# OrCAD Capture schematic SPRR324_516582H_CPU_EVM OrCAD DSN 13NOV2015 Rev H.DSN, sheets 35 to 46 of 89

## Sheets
35 SH42 - VAYU IO POWER: size B; rev: F
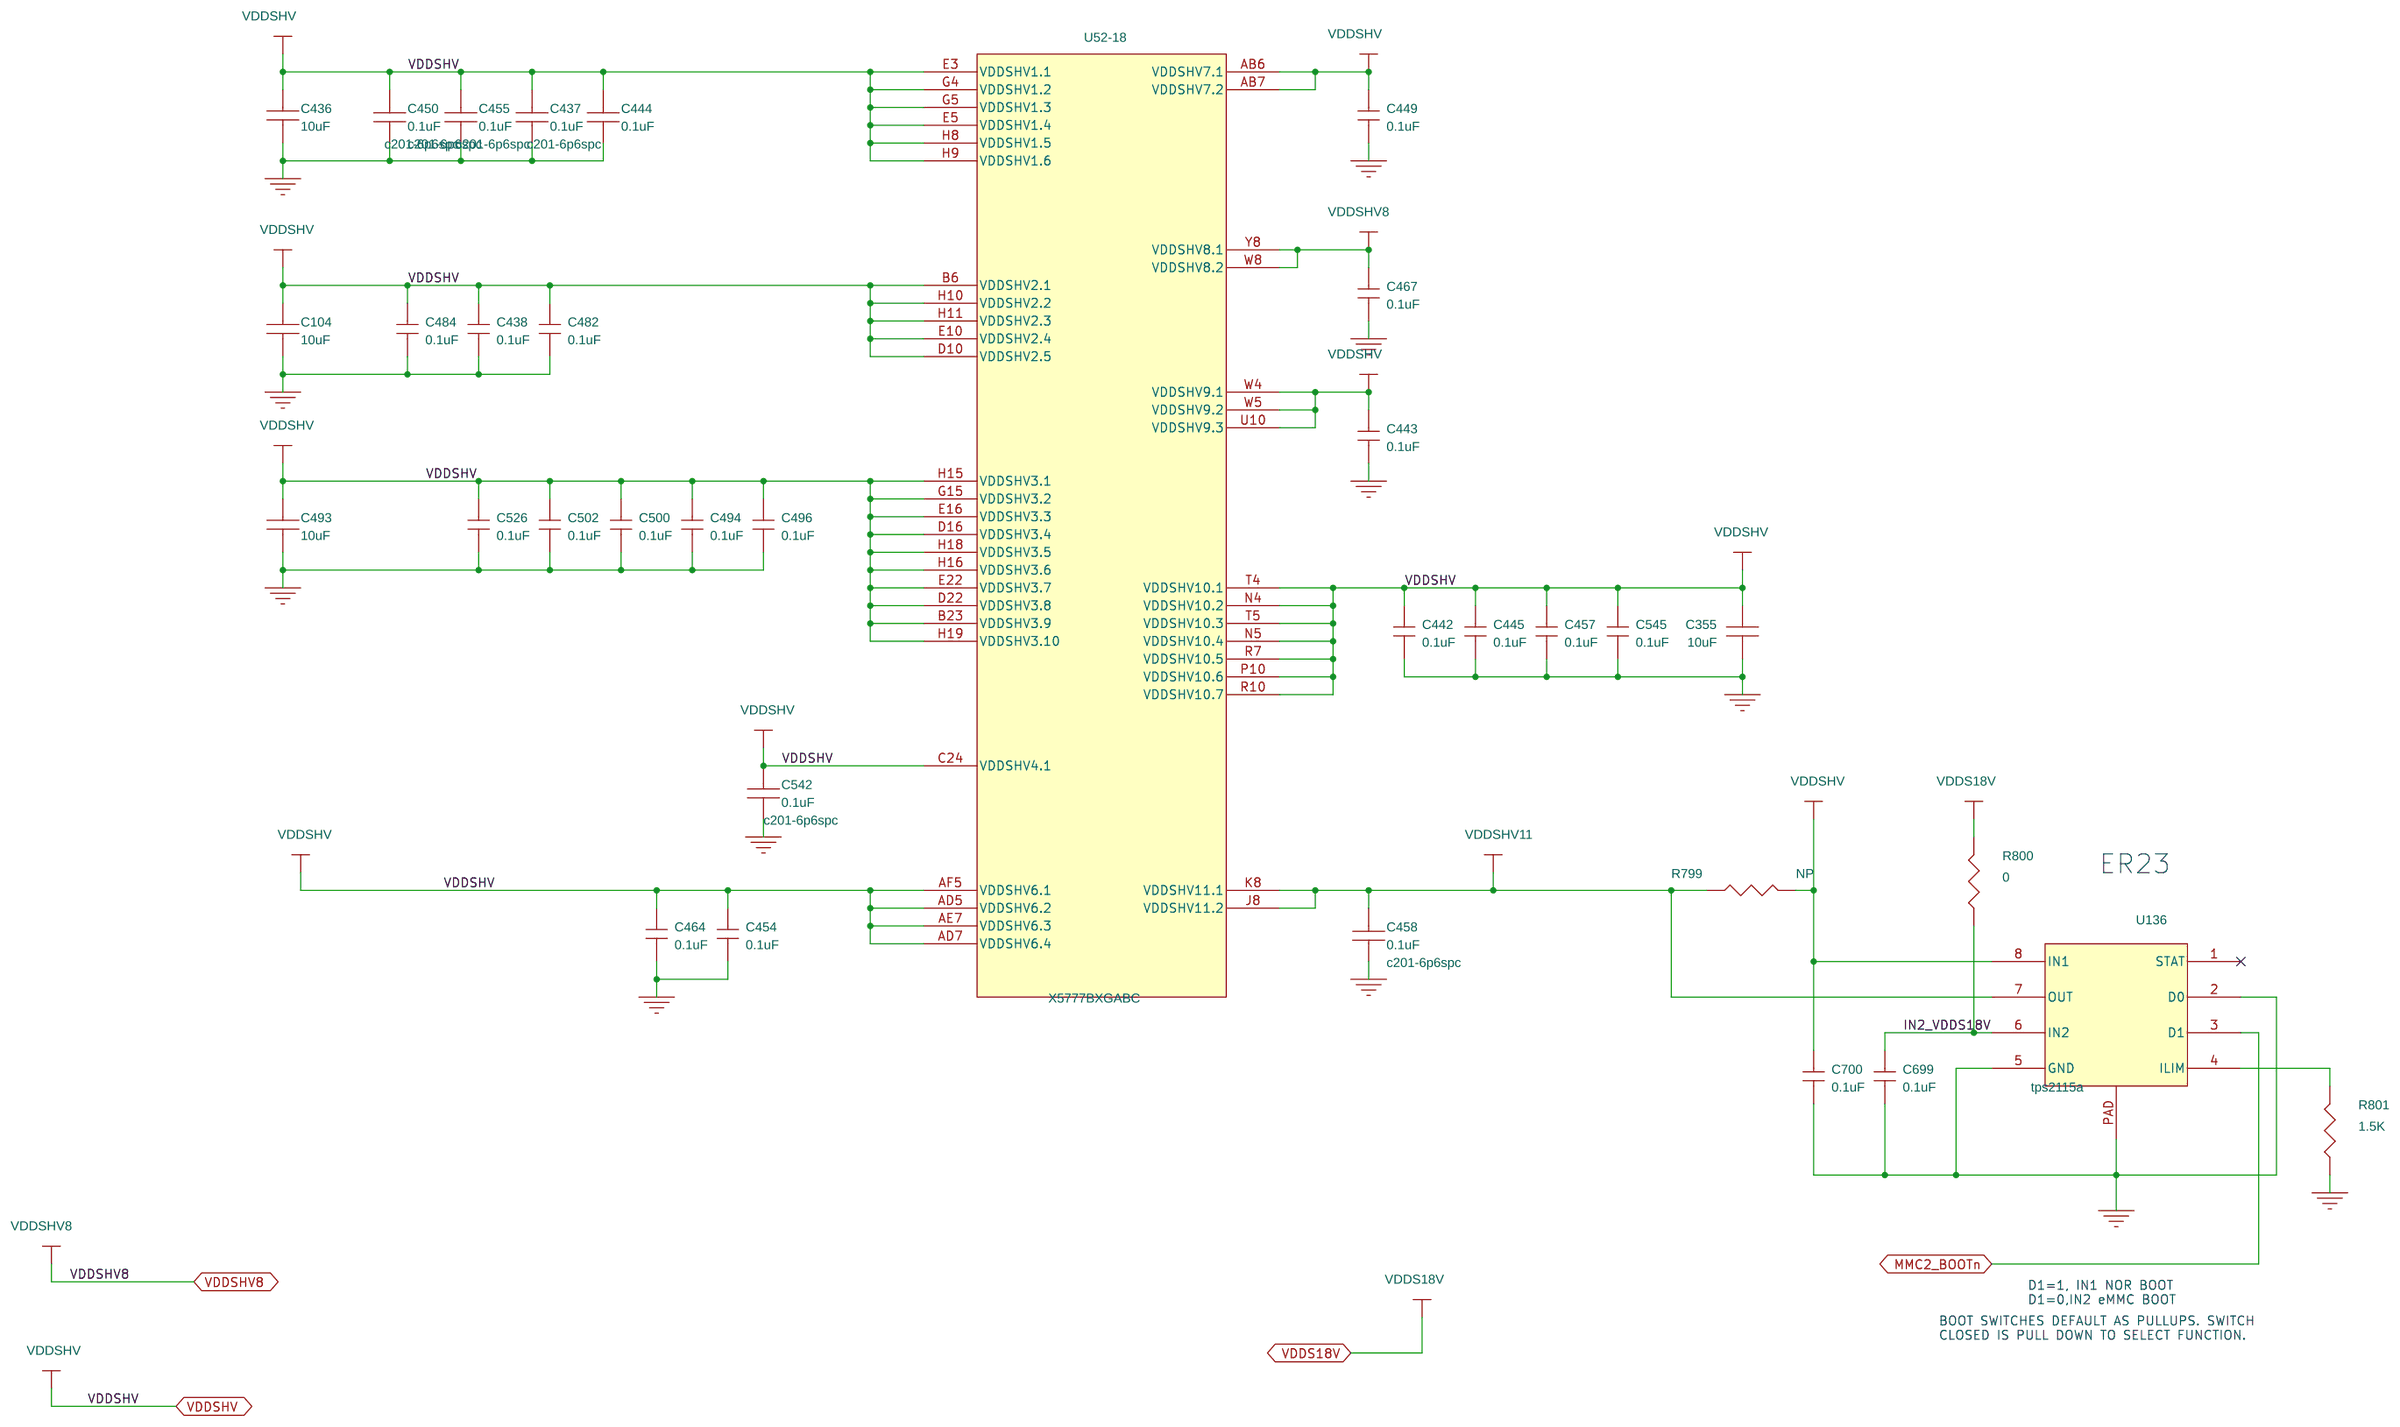
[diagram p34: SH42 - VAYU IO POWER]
36 SH43 - VAYU POWER 1V8: size B; rev: A
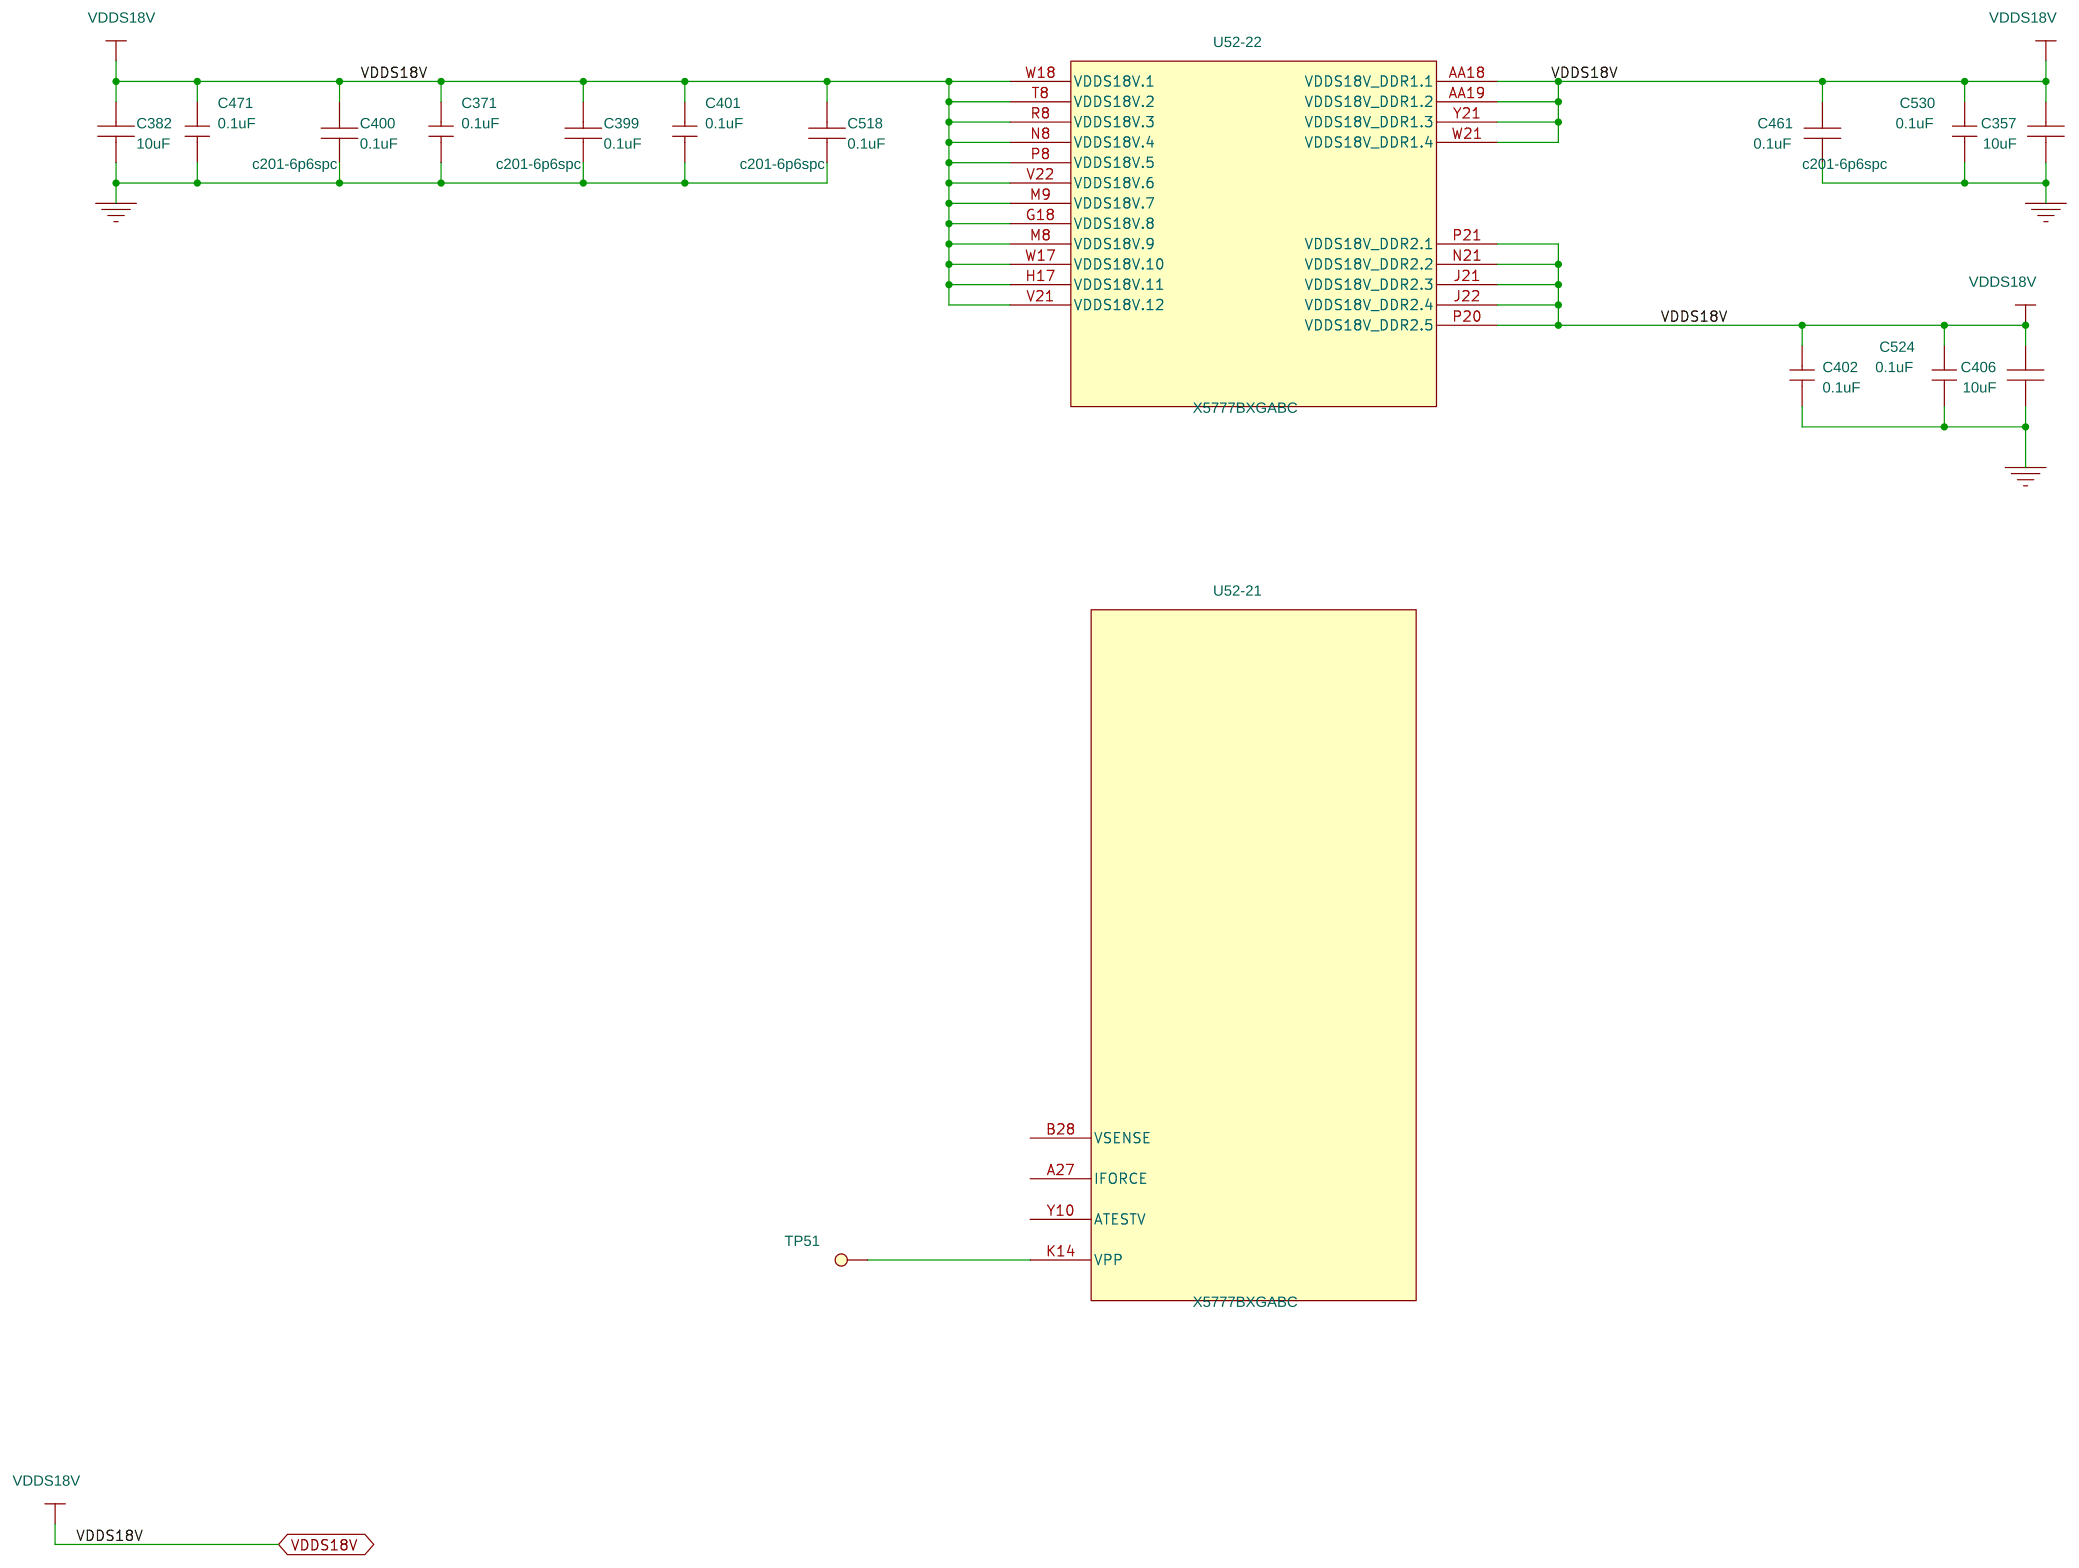
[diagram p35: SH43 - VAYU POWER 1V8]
37 SH44 - VAYU DDR POWER: size B; rev: A
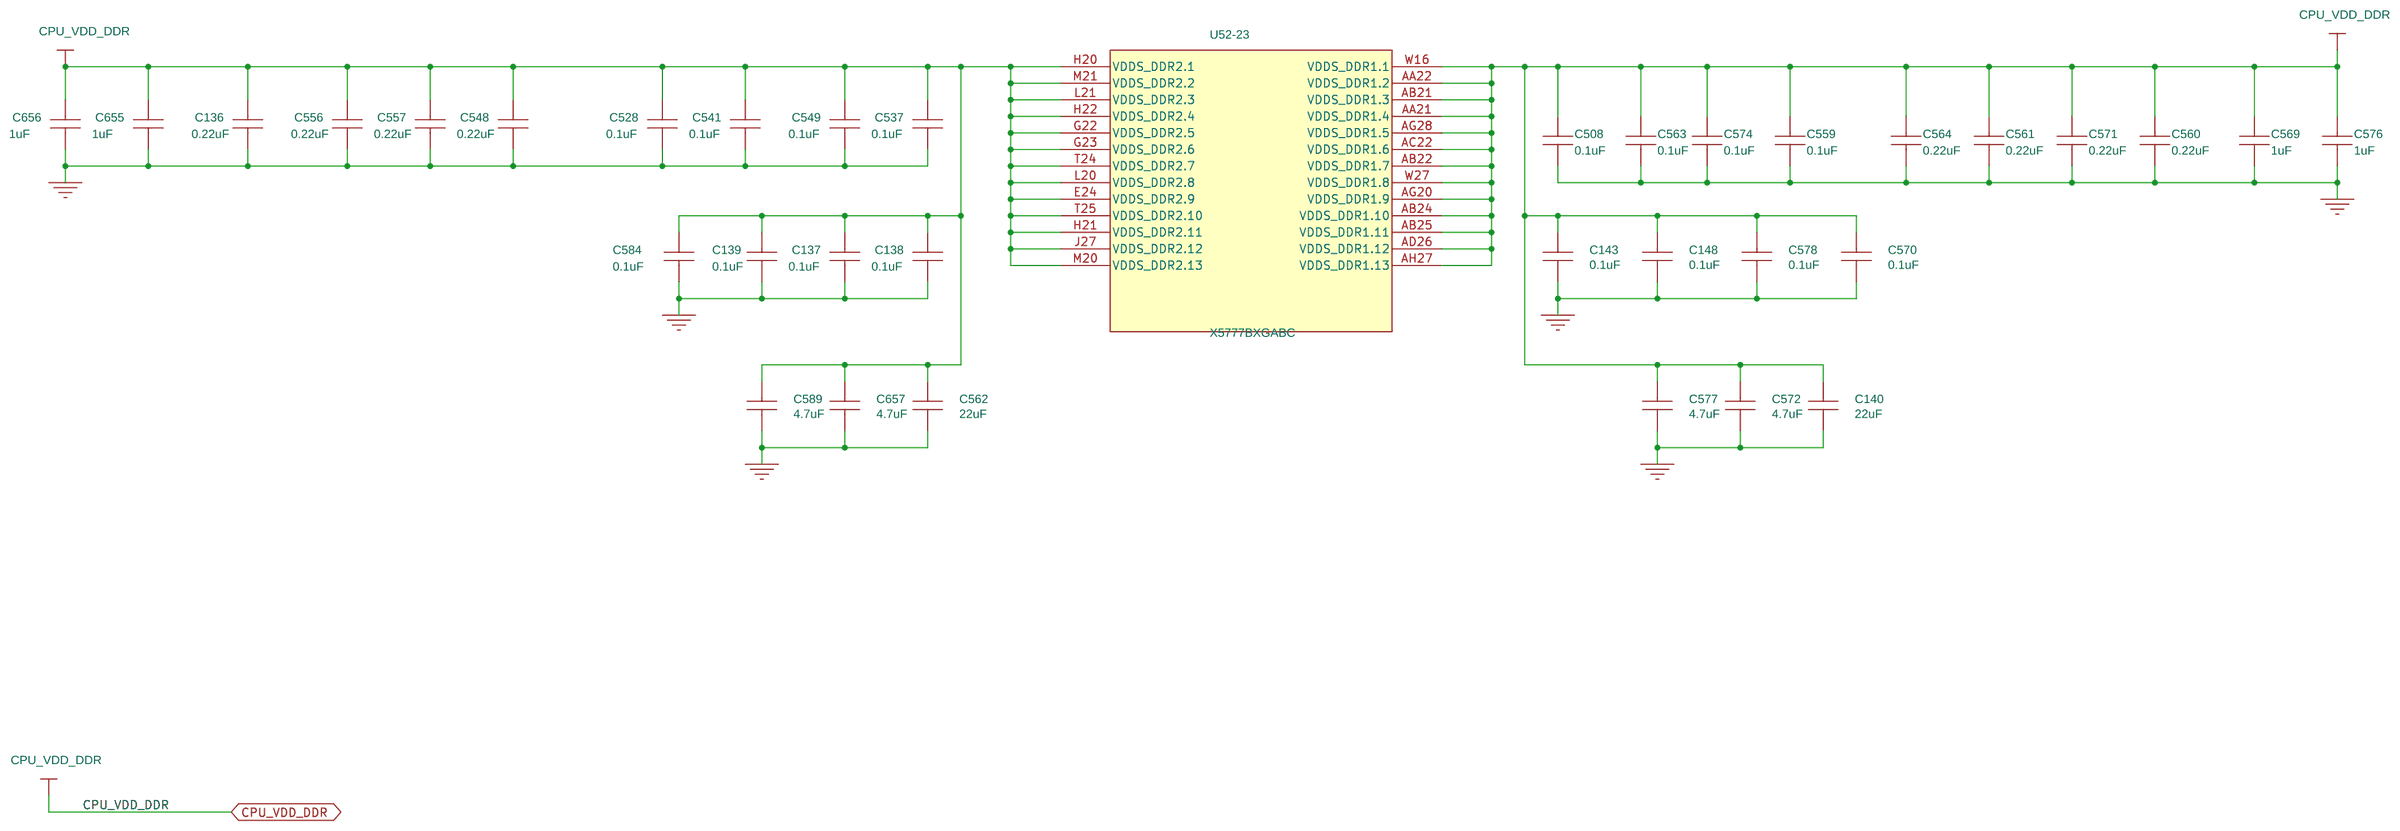
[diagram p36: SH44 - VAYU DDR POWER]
38 SH45 - VAYU 1V8A: size B; rev: A
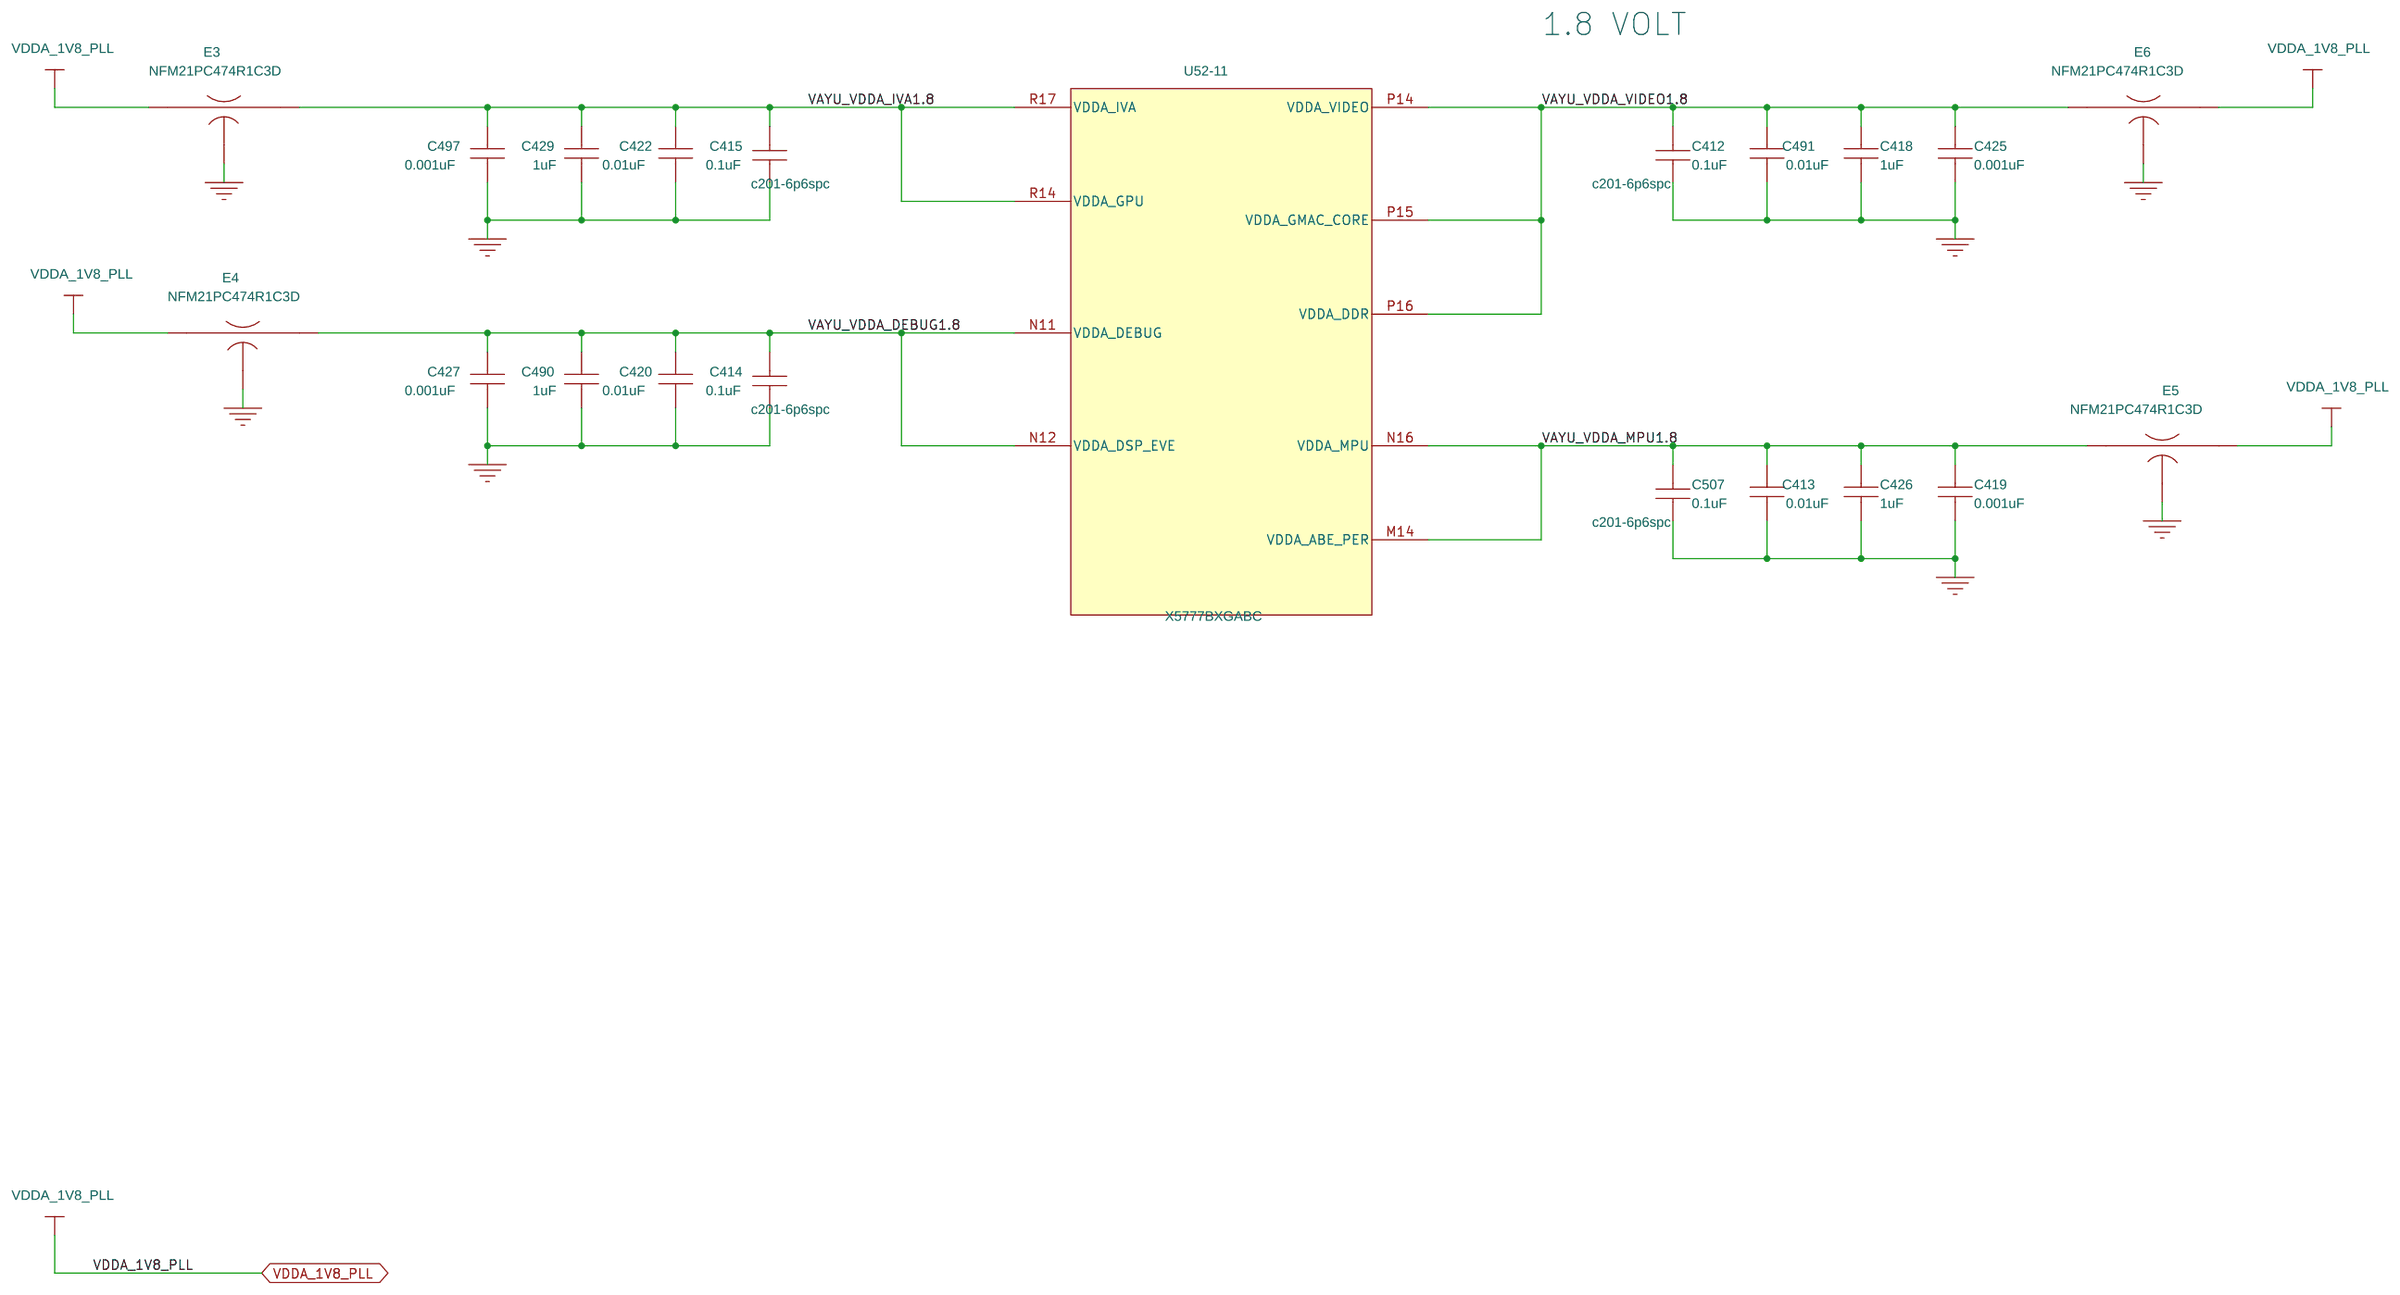
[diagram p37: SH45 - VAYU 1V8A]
39 SH46 - VAYU CORE POWER: size B; rev: A
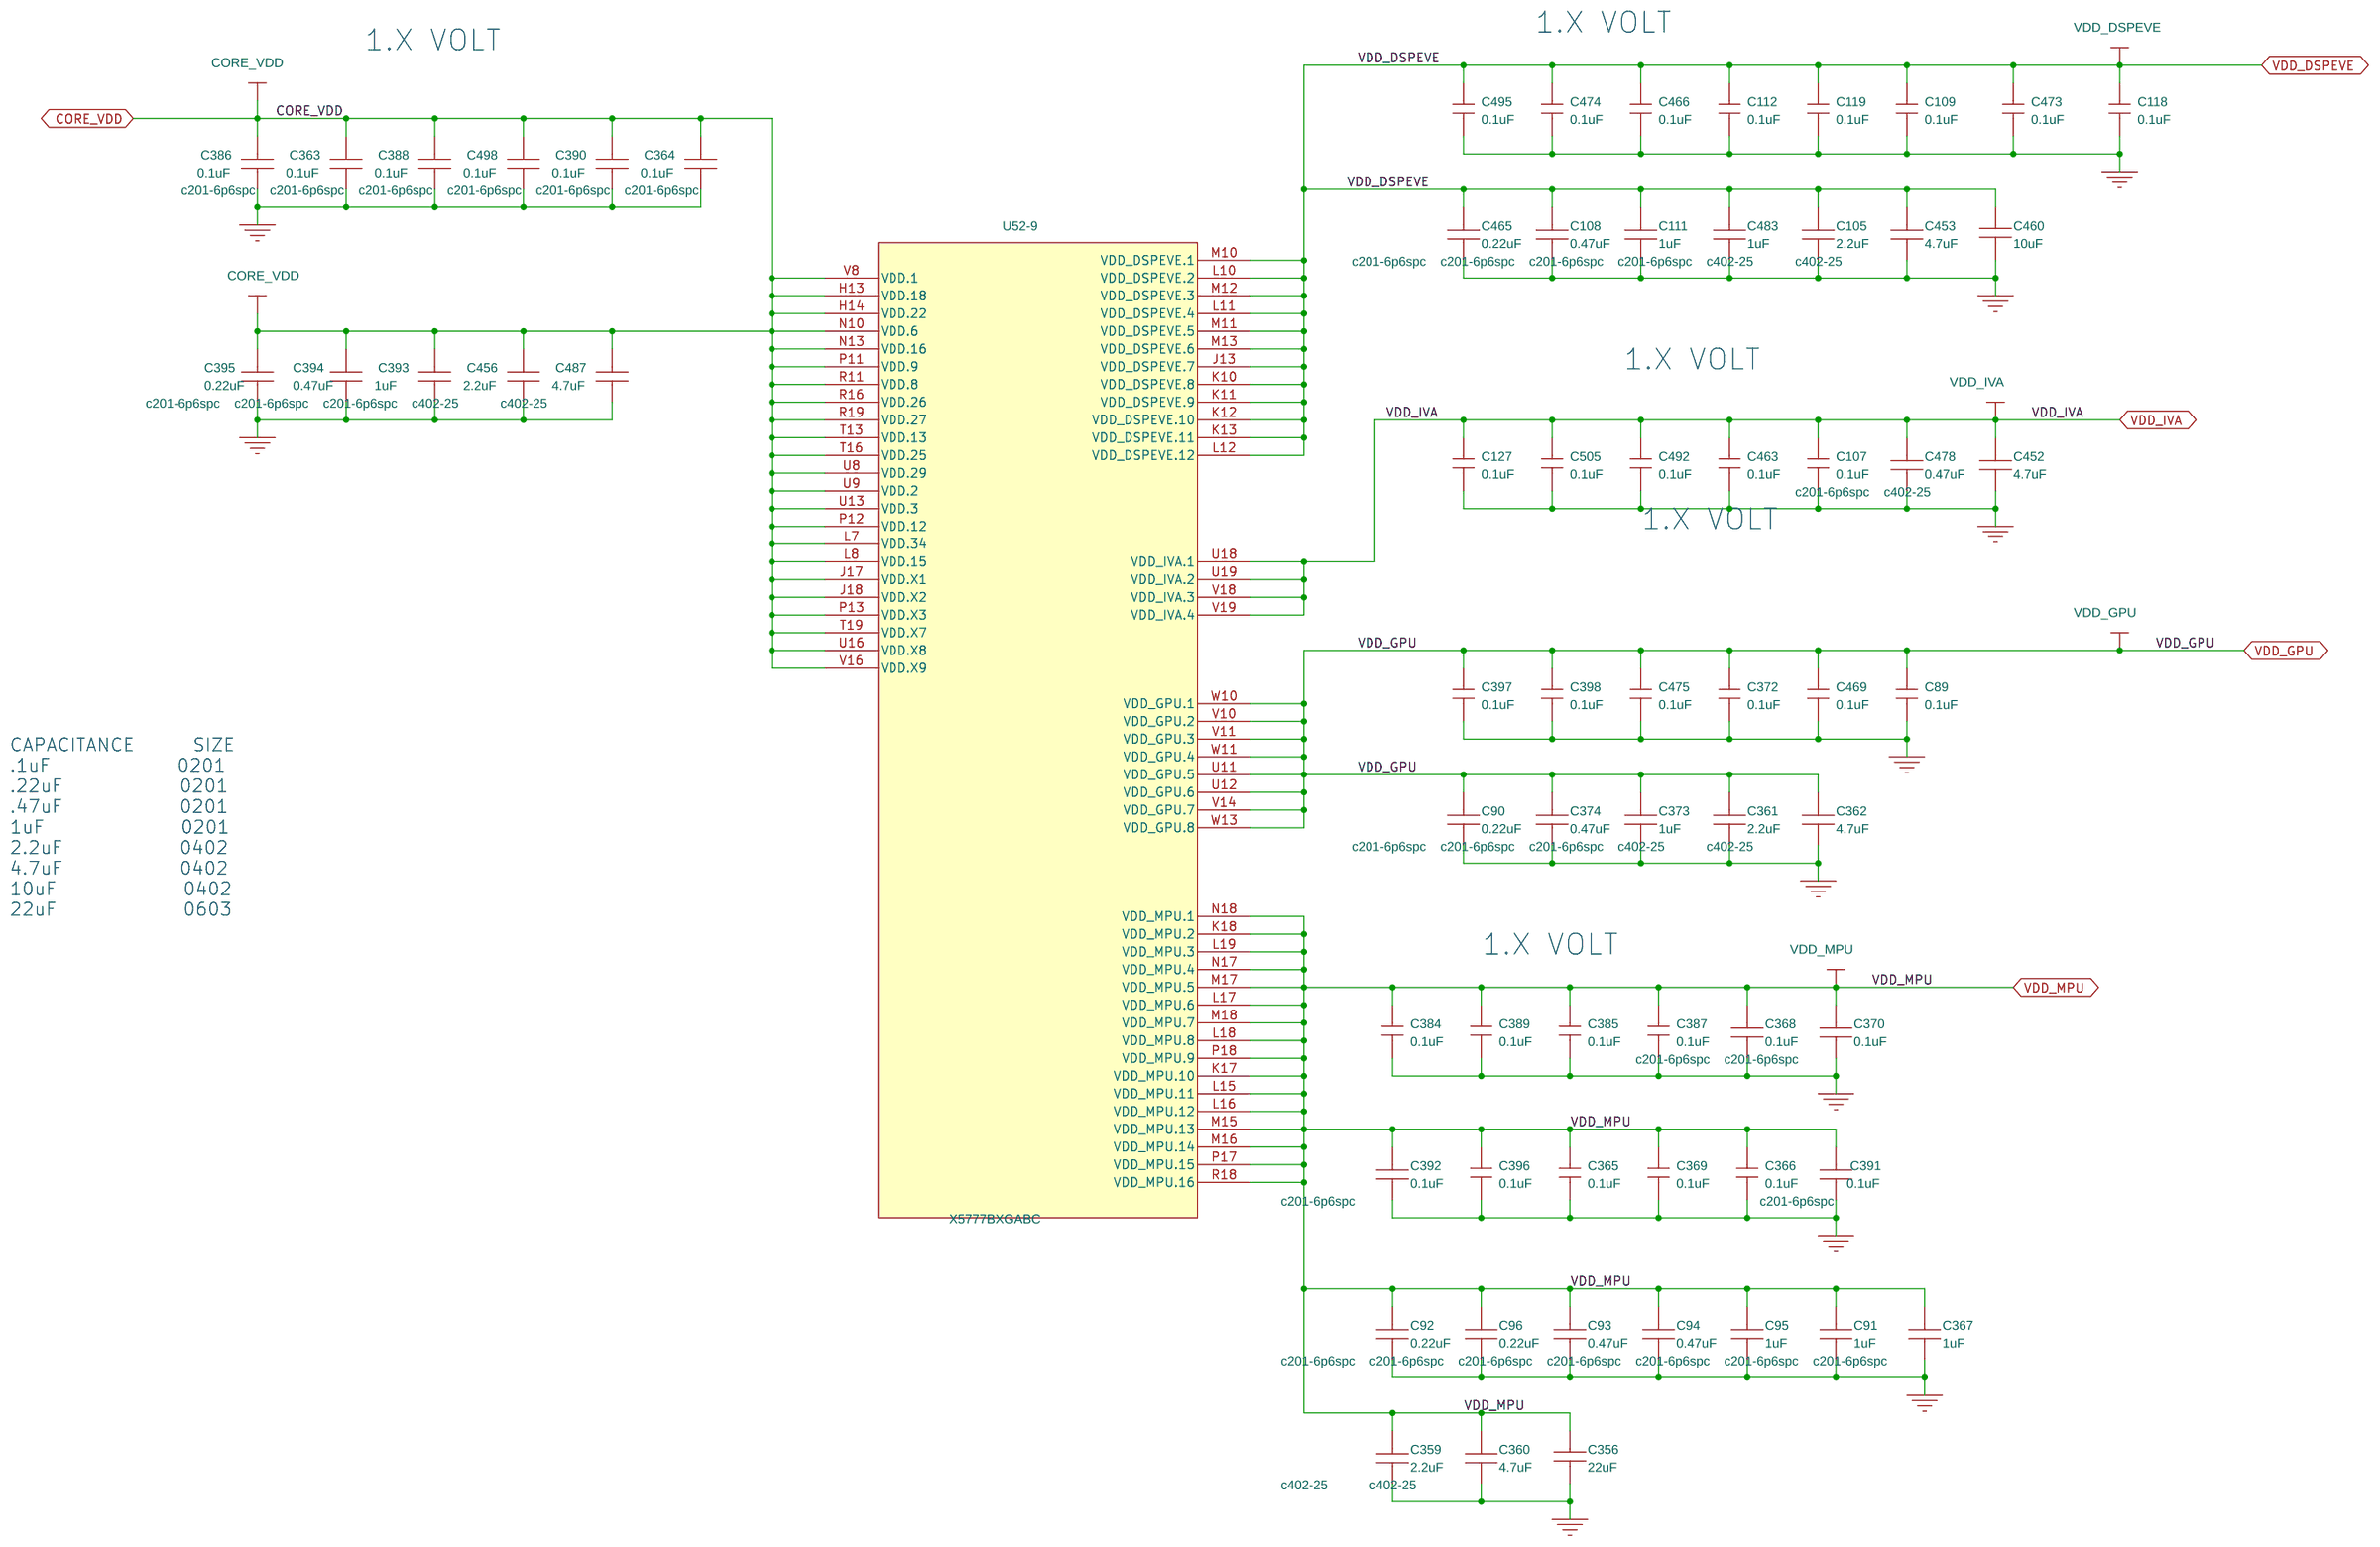
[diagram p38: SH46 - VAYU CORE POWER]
40 SH47 - VAYU GROUND PINS: size B; rev: A
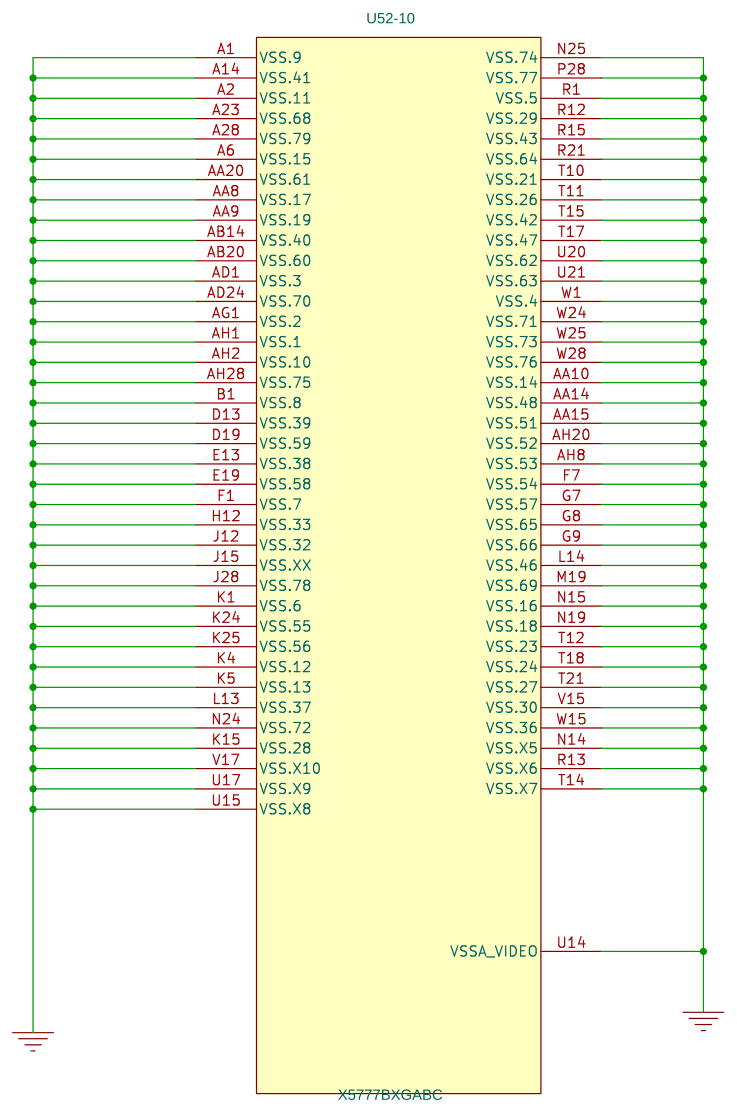
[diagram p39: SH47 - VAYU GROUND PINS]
41 SH48 - DDR3 EMIF1 TESTPOINTS: size B; rev: A
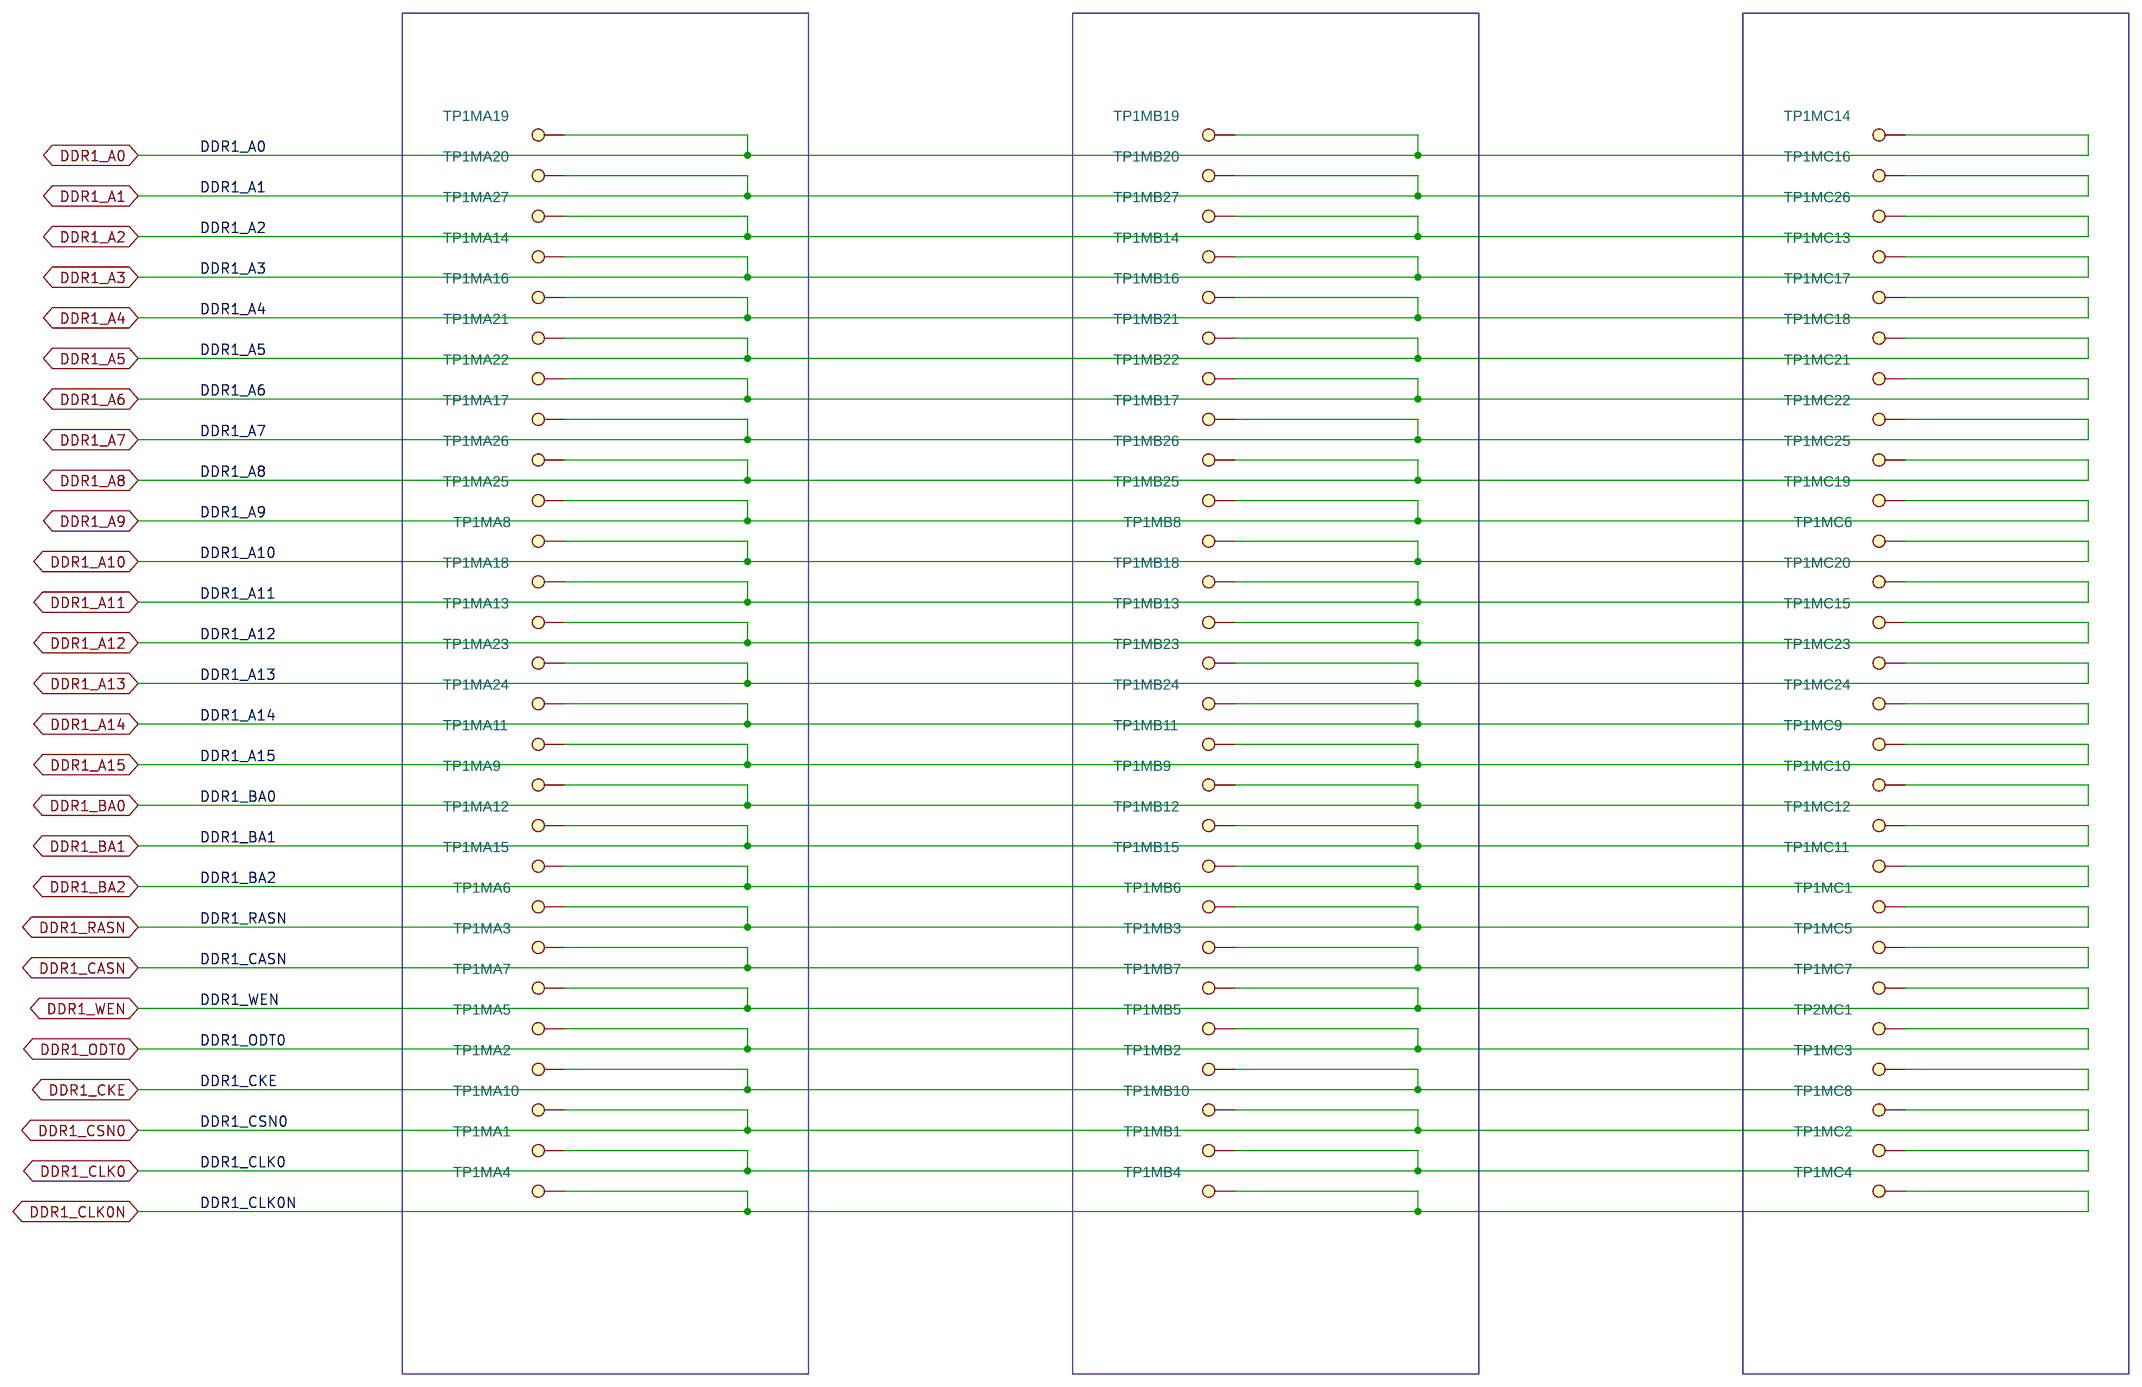
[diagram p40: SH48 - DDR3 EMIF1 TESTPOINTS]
42 SH49 - DDR3  BANK 1: size B
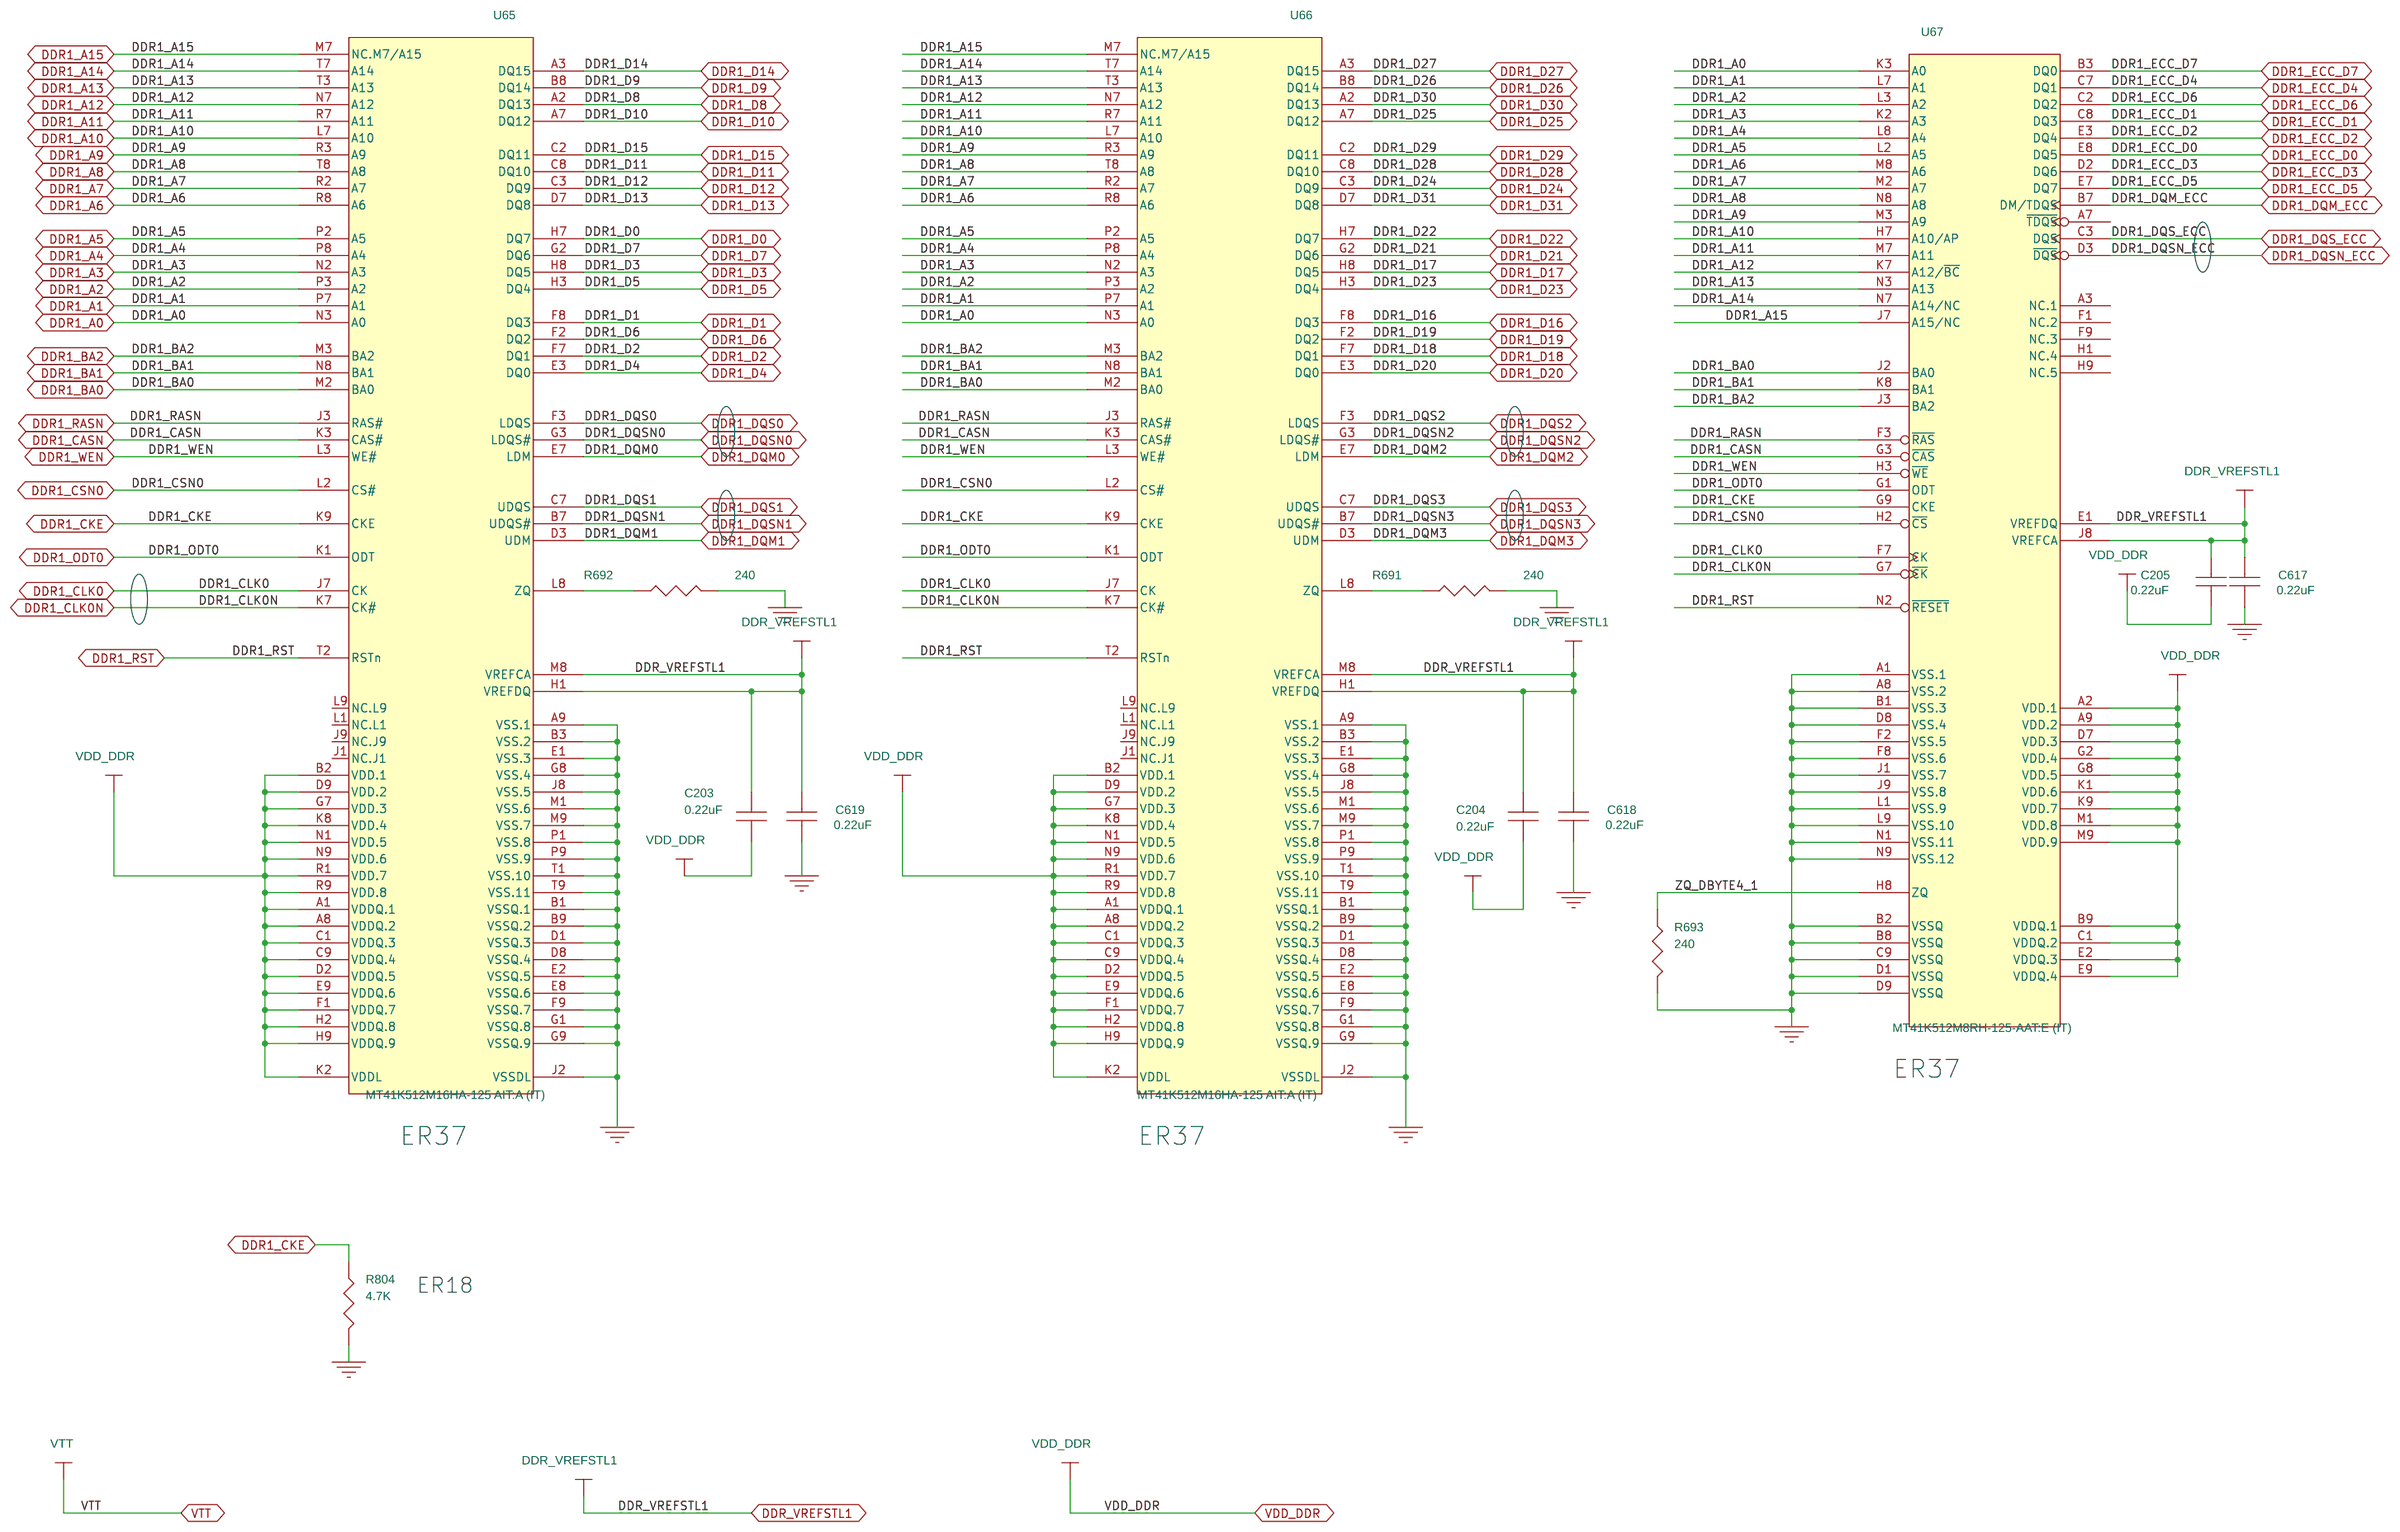
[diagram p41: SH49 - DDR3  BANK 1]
43 SH50 - DDR3 EMIF1 CAPS: size B; rev: A
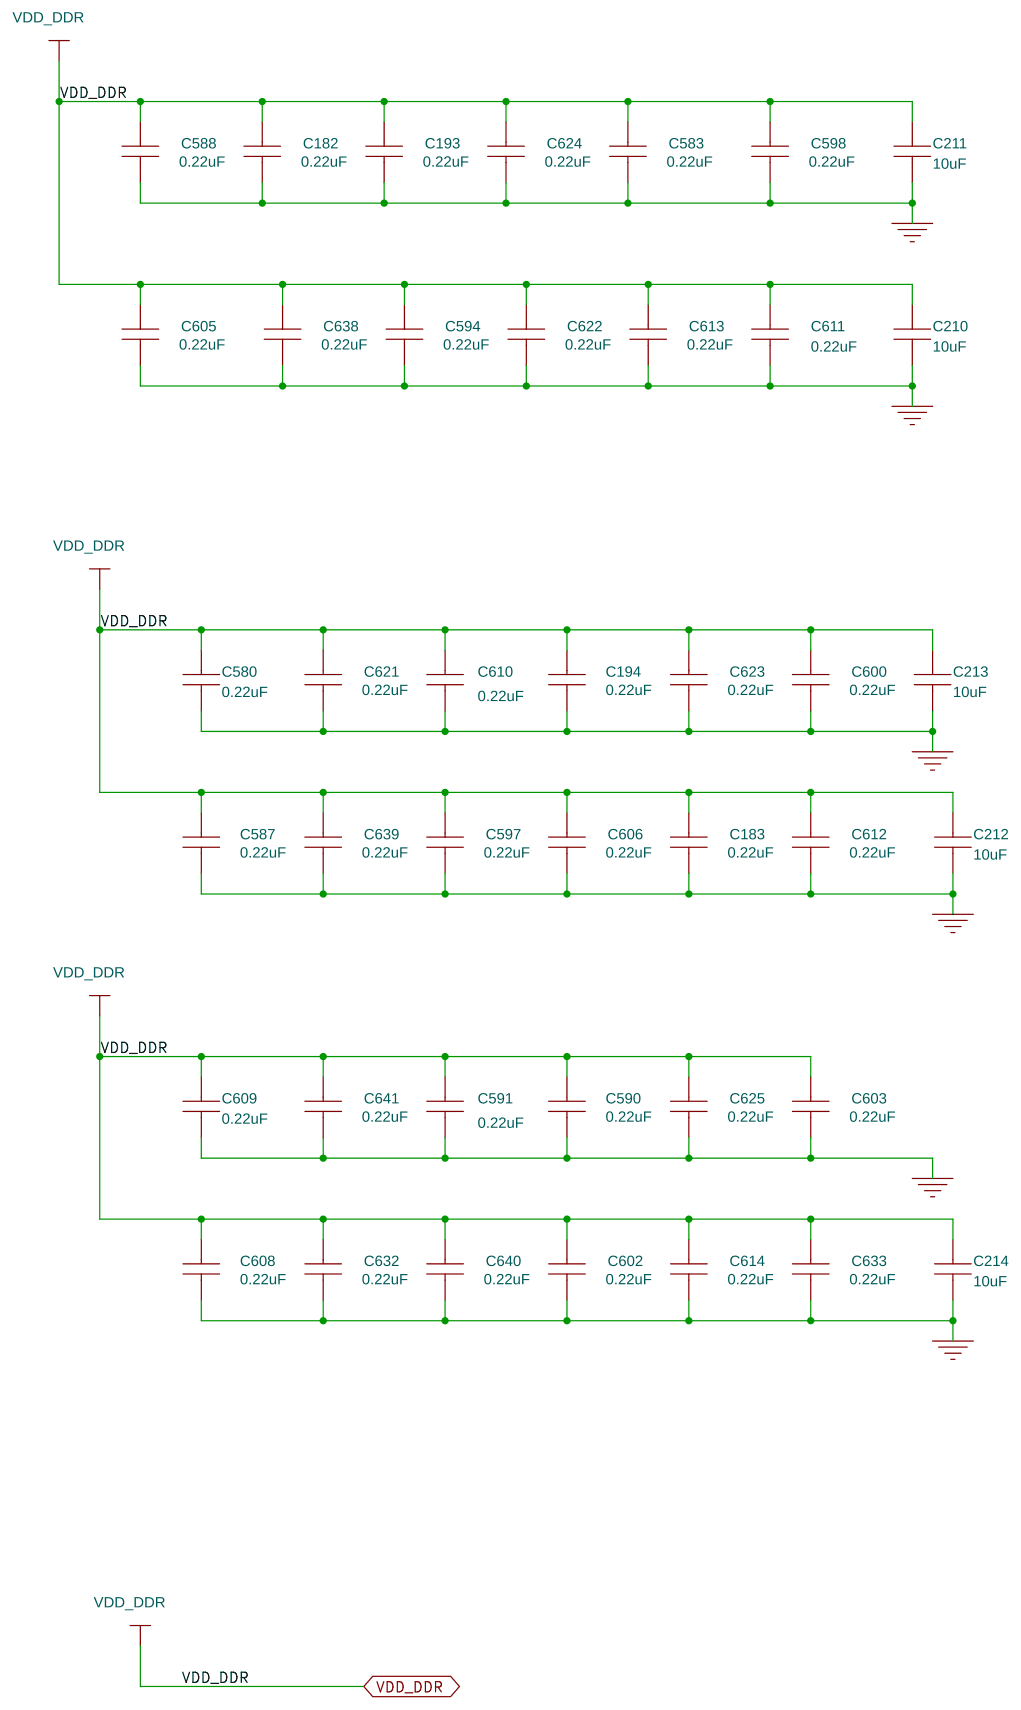
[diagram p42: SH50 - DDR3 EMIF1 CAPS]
44 SH51 - DDR3 BANK1 TERMINATION: size B; rev: A
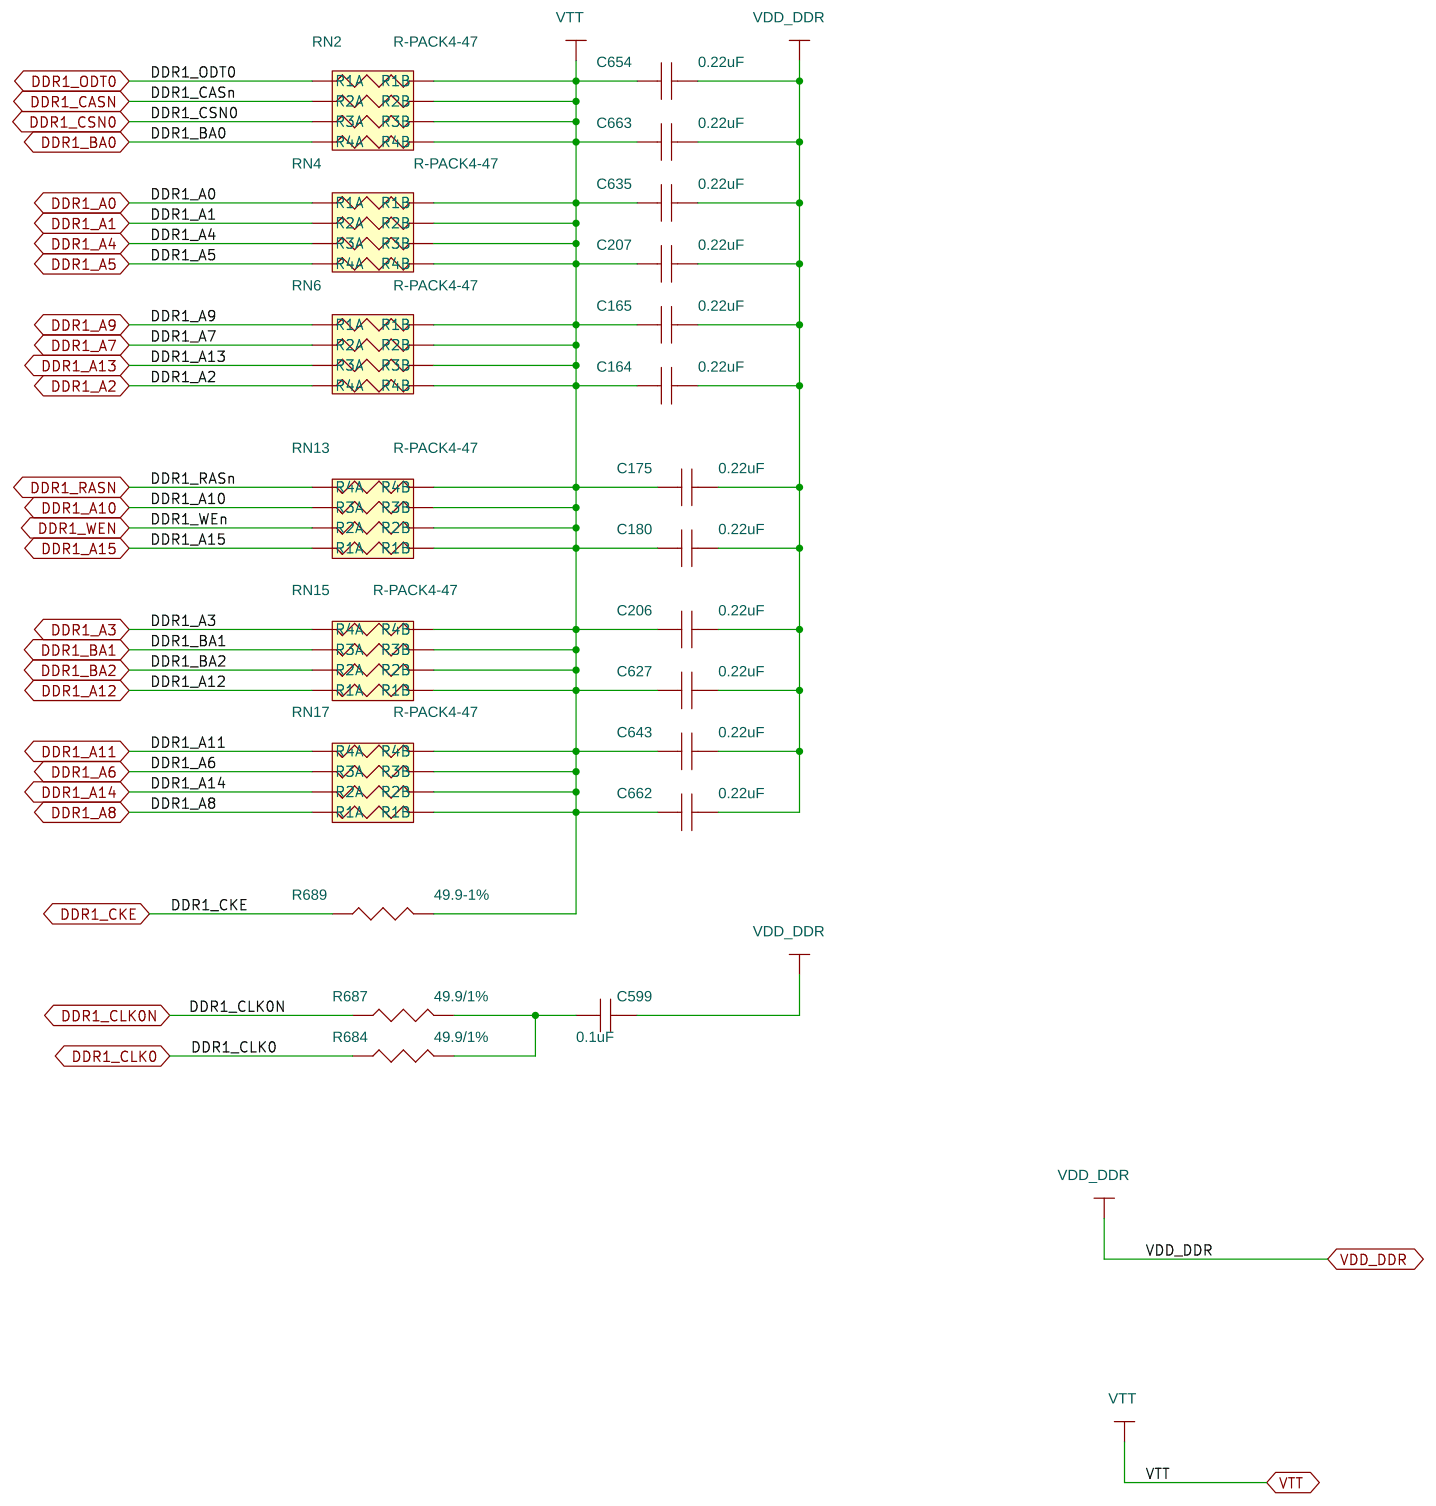
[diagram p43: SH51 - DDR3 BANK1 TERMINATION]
45 SH52 - TESTPOINTS DDR3  EMIF 2: size B; rev: A
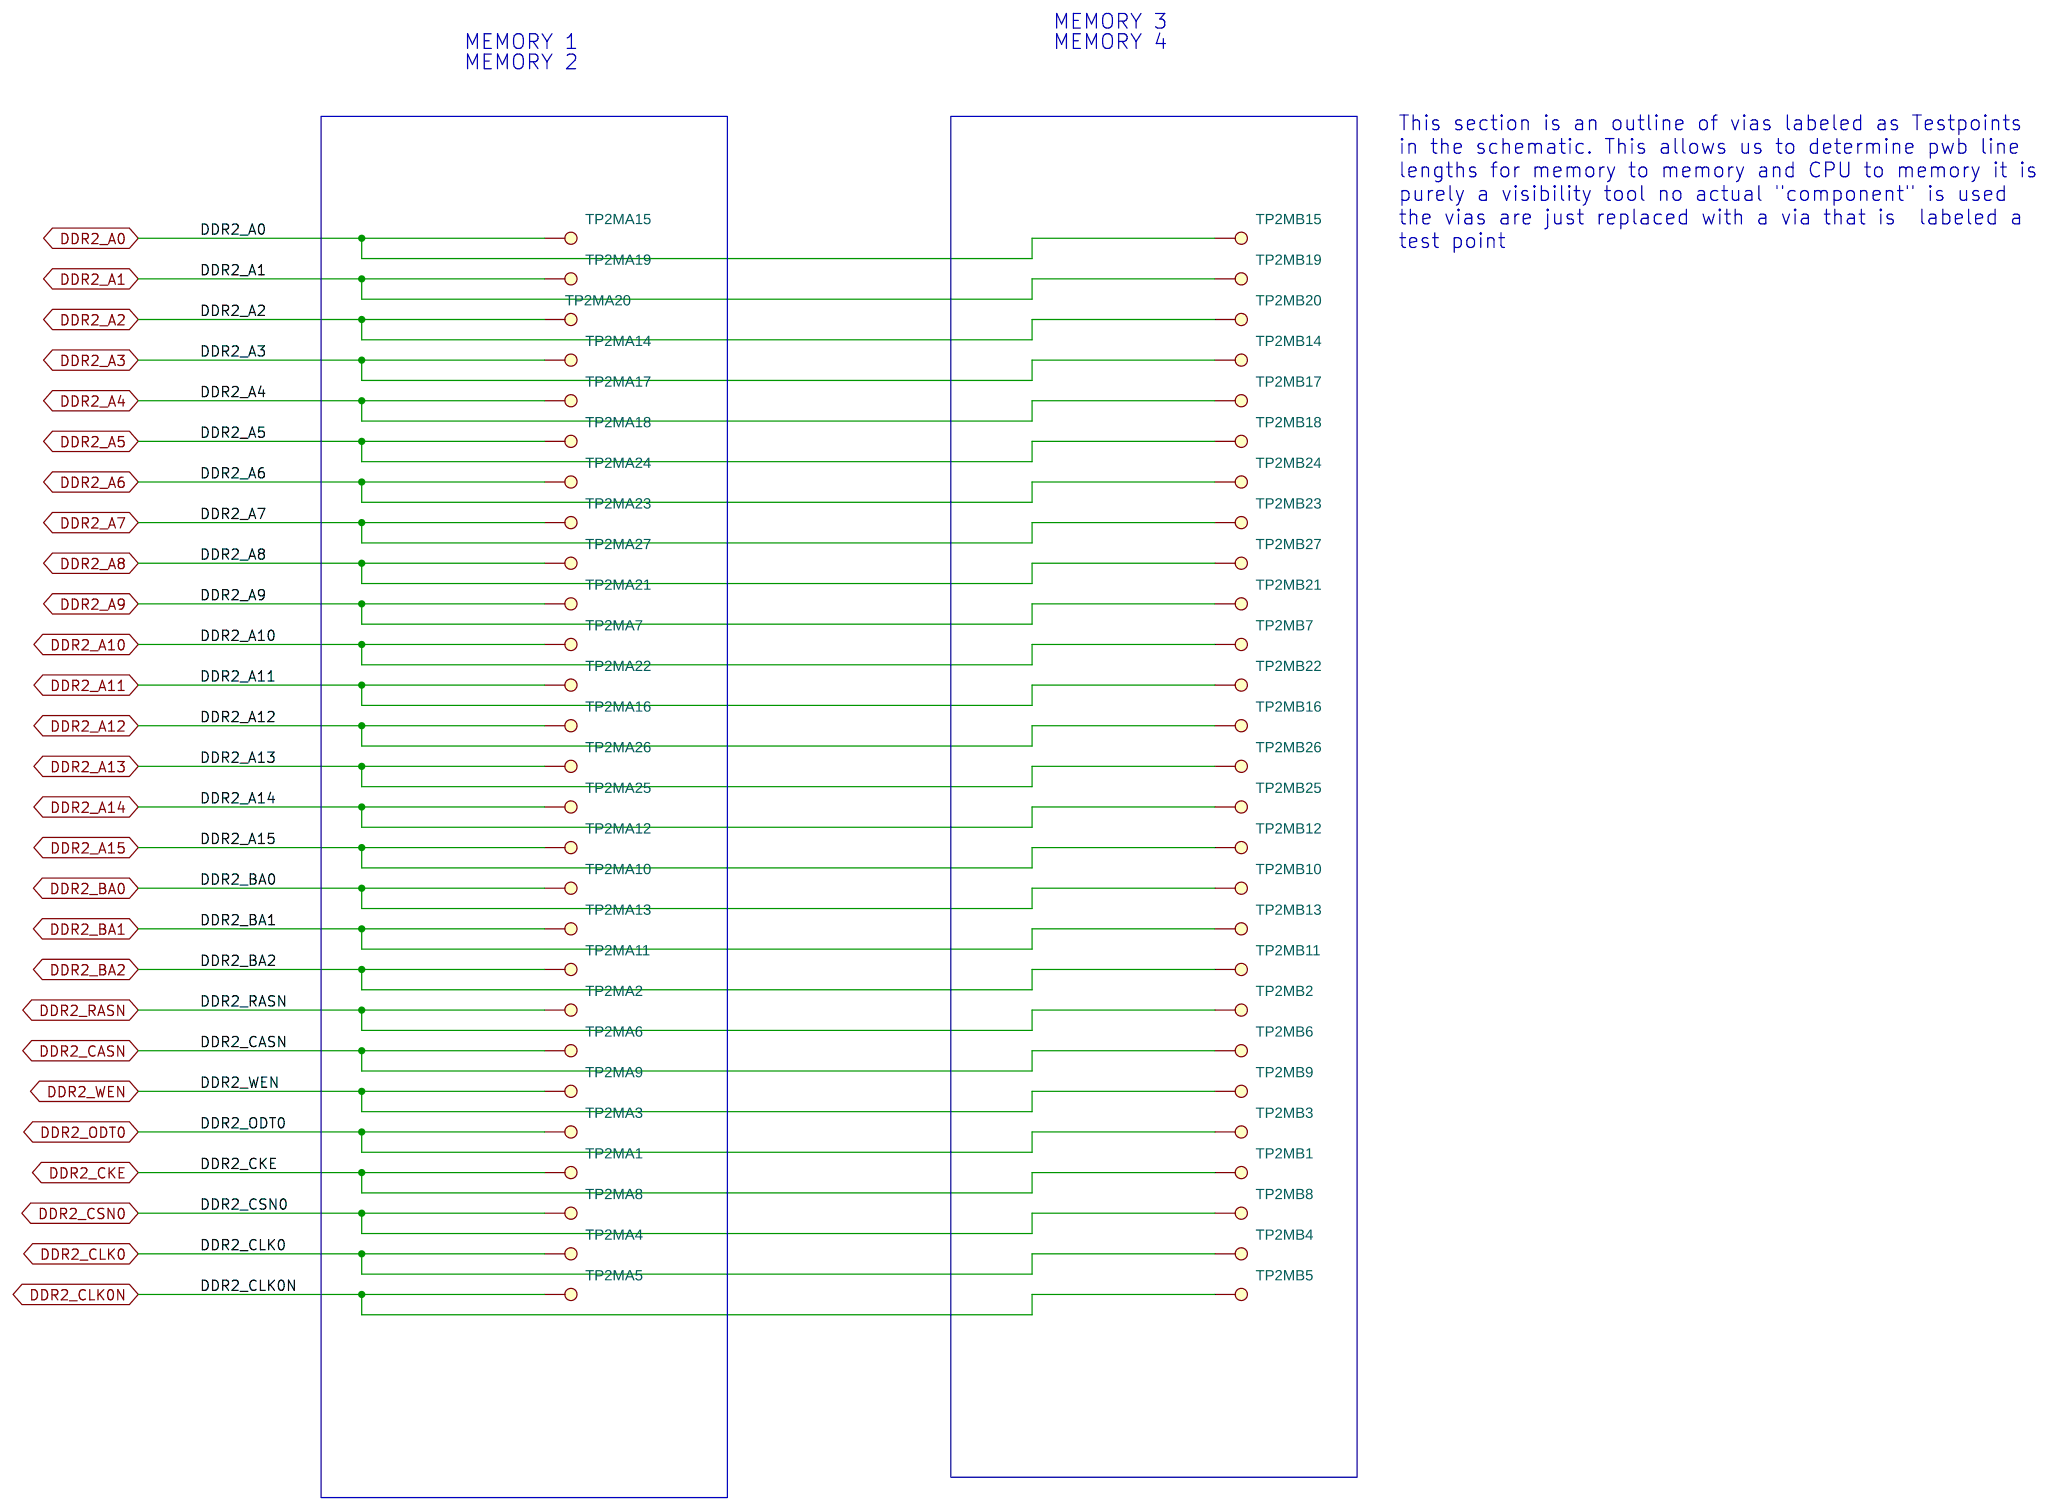
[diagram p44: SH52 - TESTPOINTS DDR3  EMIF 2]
46 SH53 - DDR3 MEMORY BANK 2: size B
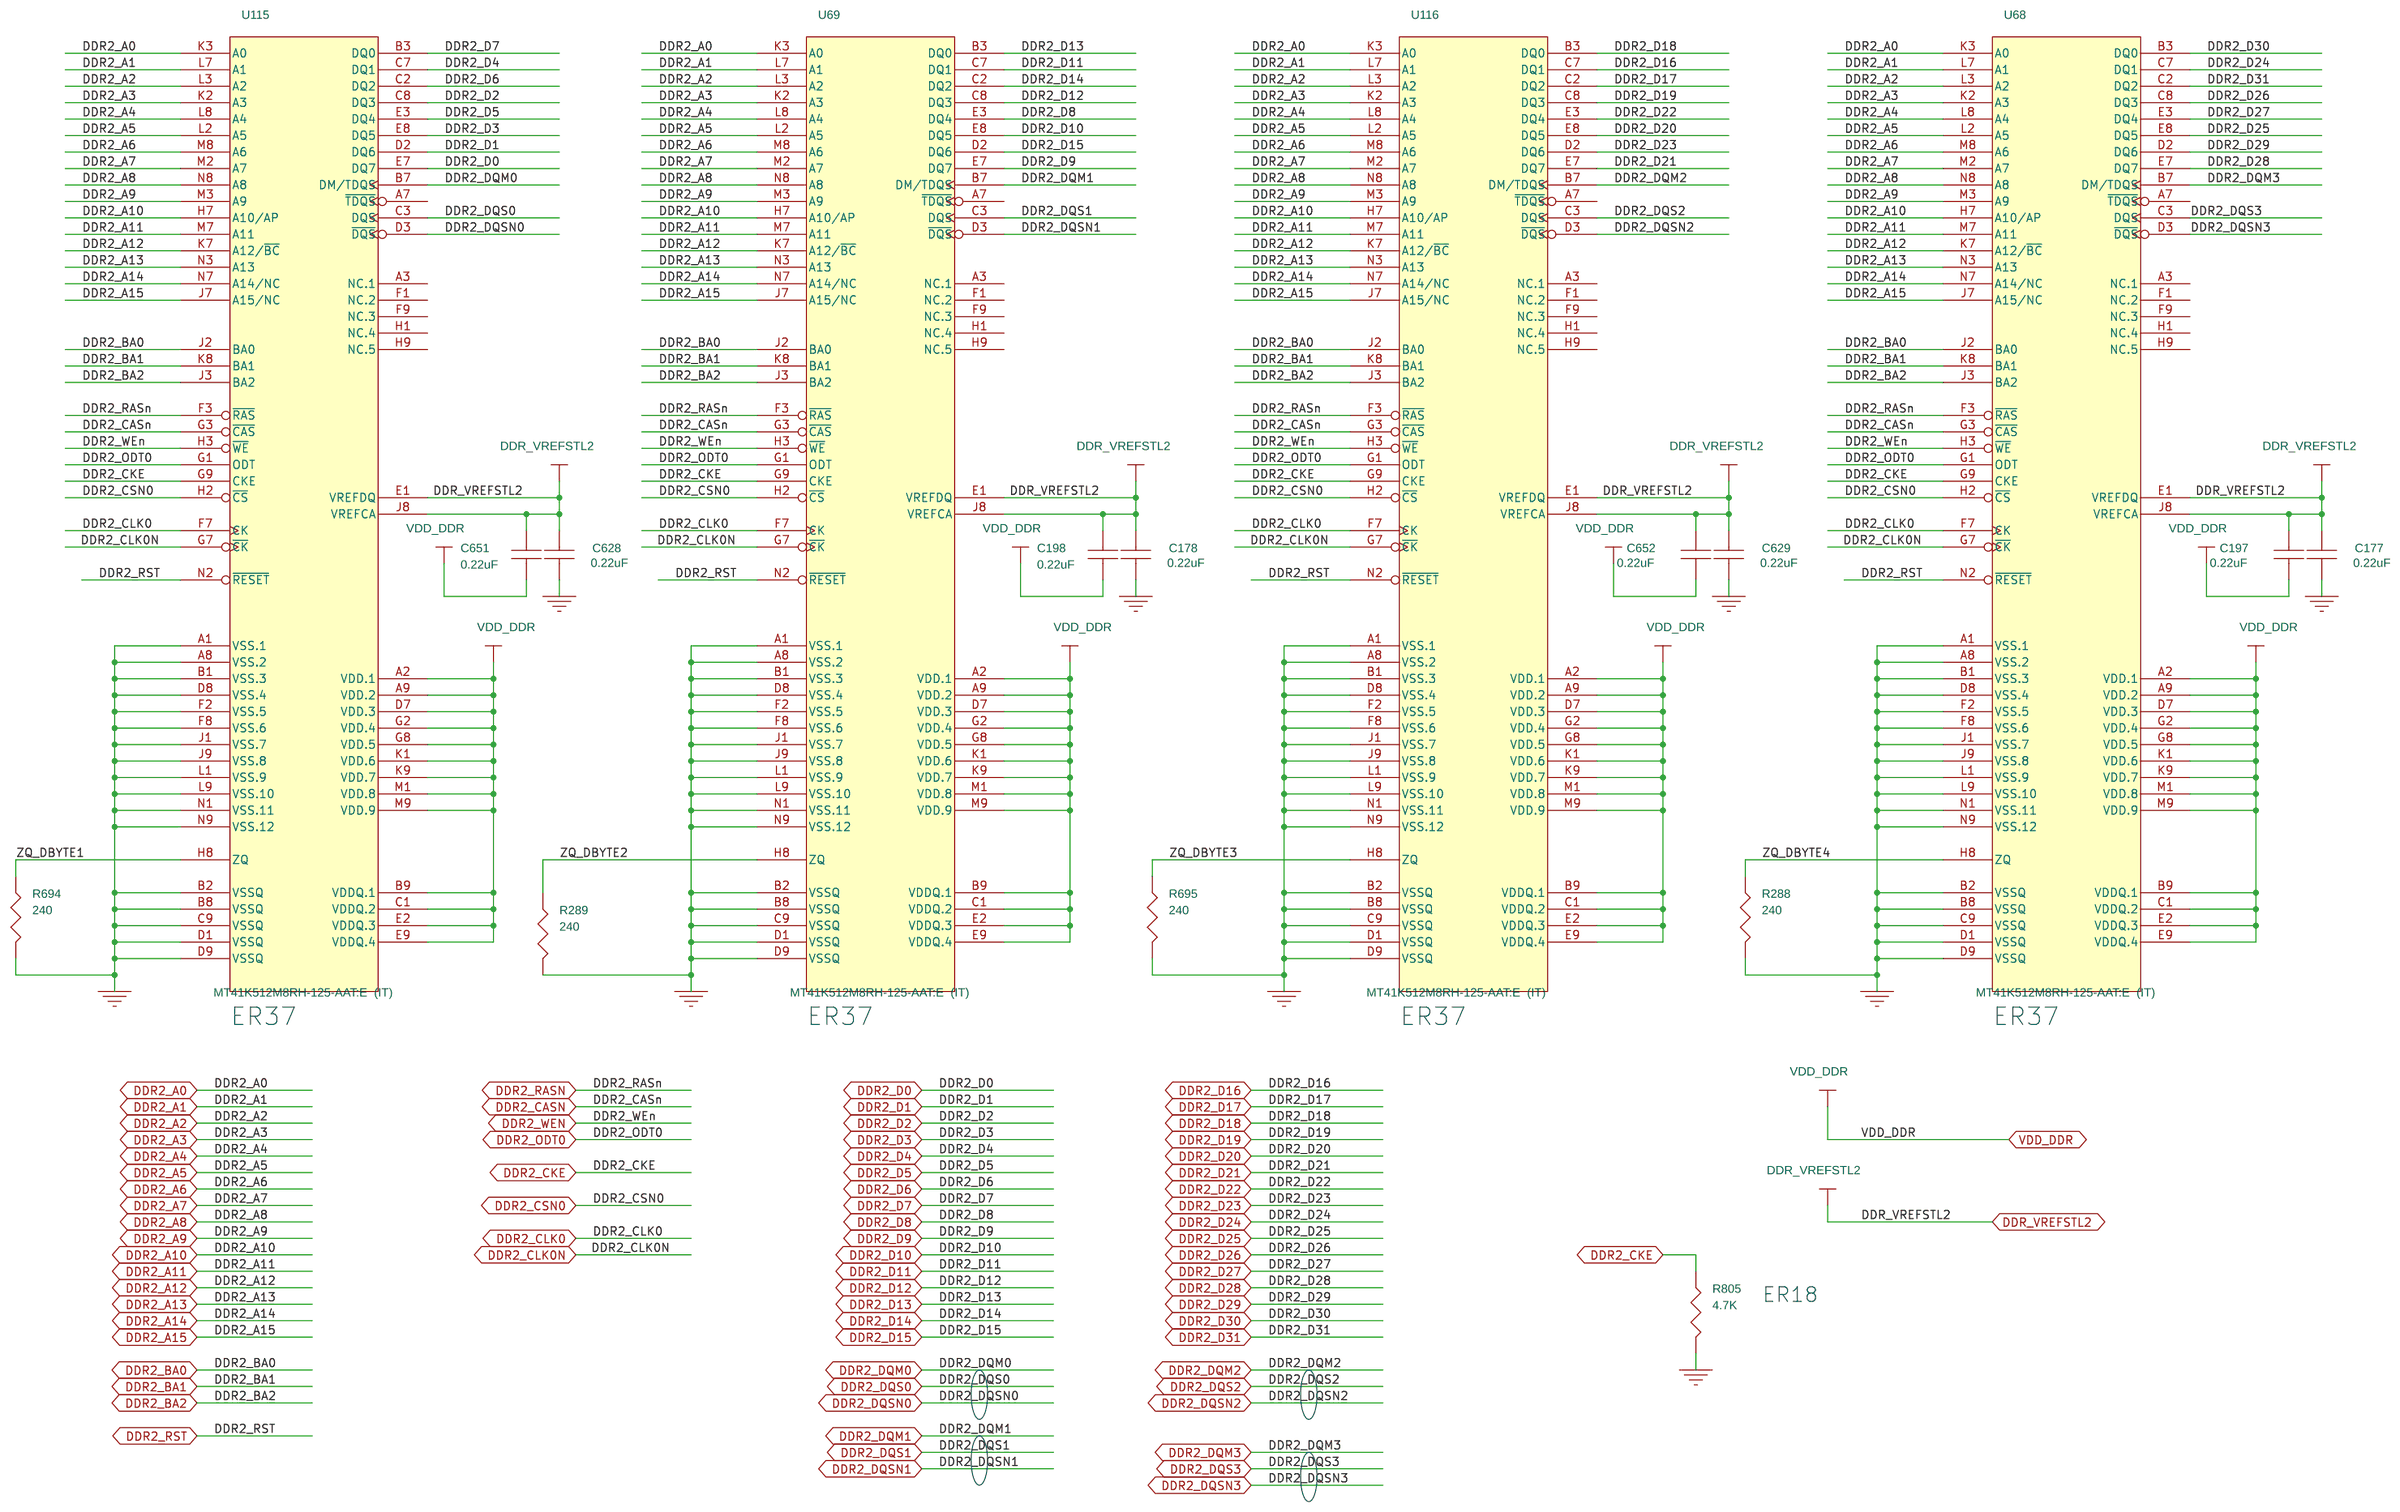
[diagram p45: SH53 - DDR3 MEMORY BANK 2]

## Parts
sheet SH28 - VAYU VOUT1 PORT LCD
U52  X5777BXGABC  [sktbga-zkk-6334-p760]  (sections -1,-10,-11,-12,-13,-14,-15,-16,-17,-18,-19,-2,-20,-21,-22,-23,-3,-4,-5,-6,-7,-8,-9)
sheet SH42 - VAYU IO POWER
C104  10uF  [c603-35x45]
C355  10uF  [c603-35x45]
C436  10uF  [c603-35x45]
C437  0.1uF  [c201-6p6spc]
C438  0.1uF  [c201-6p6spc]
C442  0.1uF  [c201-6p6spc]
C443  0.1uF  [c201-6p6spc]
C444  0.1uF  [c201-6p6spc]
C445  0.1uF  [c201-6p6spc]
C449  0.1uF  [c201-6p6spc]
C450  0.1uF  [c201-6p6spc]
C454  0.1uF  [c201-6p6spc]
C455  0.1uF  [c201-6p6spc]
C457  0.1uF  [c201-6p6spc]
C458  0.1uF  [c201-6p6spc]
C464  0.1uF  [c201-6p6spc]
C467  0.1uF  [c201-6p6spc]
C482  0.1uF  [c201-6p6spc]
C484  0.1uF  [c201-6p6spc]
C493  10uF  [c603-35x45]
C494  0.1uF  [c201-6p6spc]
C496  0.1uF  [c201-6p6spc]
C500  0.1uF  [c201-6p6spc]
C502  0.1uF  [c201-6p6spc]
C526  0.1uF  [c201-6p6spc]
C542  0.1uF  [c201-6p6spc]
C545  0.1uF  [c201-6p6spc]
C699  0.1uF  [c201-6p6spc]
C700  0.1uF  [c201-6p6spc]
R799  NP  [r402-25]
R800  0  [r402-25]
R801  1.5K  [r402-25]
U136  tps2115a  [drb8-14x33-pad]
sheet SH43 - VAYU POWER 1V8
C357  10uF  [c603-35x45]
C371  0.1uF  [c201-6p6spc]
C382  10uF  [c603-35x45]
C399  0.1uF  [c201-6p6spc]
C400  0.1uF  [c201-6p6spc]
C401  0.1uF  [c201-6p6spc]
C402  0.1uF  [c201-6p6spc]
C406  10uF  [c603-35x45]
C461  0.1uF  [c201-6p6spc]
C471  0.1uF  [c201-6p6spc]
C518  0.1uF  [c201-6p6spc]
C524  0.1uF  [c201-6p6spc]
C530  0.1uF  [c201-6p6spc]
TP51  TestPoint1  [tp1-18rd8]
sheet SH44 - VAYU DDR POWER
C136  0.22uF  [c201-6p6spc]
C137  0.1uF  [c201-6p6spc]
C138  0.1uF  [c201-6p6spc]
C139  0.1uF  [c201-6p6spc]
C140  22uF  [c603-35x45]
C143  0.1uF  [c201-6p6spc]
C148  0.1uF  [c201-6p6spc]
C508  0.1uF  [c201-6p6spc]
C528  0.1uF  [c201-6p6spc]
C537  0.1uF  [c201-6p6spc]
C541  0.1uF  [c201-6p6spc]
C548  0.22uF  [c201-6p6spc]
C549  0.1uF  [c201-6p6spc]
C556  0.22uF  [c201-6p6spc]
C557  0.22uF  [c201-6p6spc]
C559  0.1uF  [c201-6p6spc]
C560  0.22uF  [c201-6p6spc]
C561  0.22uF  [c201-6p6spc]
C562  22uF  [c603-35x45]
C563  0.1uF  [c201-6p6spc]
C564  0.22uF  [c201-6p6spc]
C569  1uF  [c402-25]
C570  0.1uF  [c201-6p6spc]
C571  0.22uF  [c201-6p6spc]
C572  4.7uF  [c402-25]
C574  0.1uF  [c201-6p6spc]
C576  1uF  [c402-25]
C577  4.7uF  [c402-25]
C578  0.1uF  [c201-6p6spc]
C584  0.1uF  [c201-6p6spc]
C589  4.7uF  [c402-25]
C655  1uF  [c402-25]
C656  1uF  [c402-25]
C657  4.7uF  [c402-25]
sheet SH45 - VAYU 1V8A
C412  0.1uF  [c201-6p6spc]
C413  0.01uF  [c201-6p6spc]
C414  0.1uF  [c201-6p6spc]
C415  0.1uF  [c201-6p6spc]
C418  1uF  [c201-6p6spc]
C419  0.001uF  [c201-6p6spc]
C420  0.01uF  [c201-6p6spc]
C422  0.01uF  [c201-6p6spc]
C425  0.001uF  [c201-6p6spc]
C426  1uF  [c201-6p6spc]
C427  0.001uF  [c201-6p6spc]
C429  1uF  [c201-6p6spc]
C490  1uF  [c201-6p6spc]
C491  0.01uF  [c201-6p6spc]
C497  0.001uF  [c201-6p6spc]
C507  0.1uF  [c201-6p6spc]
E3  NFM21PC474R1C3D  [emi-NFM21p]
E4  NFM21PC474R1C3D  [emi-NFM21p]
E5  NFM21PC474R1C3D  [emi-NFM21p]
E6  NFM21PC474R1C3D  [emi-NFM21p]
sheet SH46 - VAYU CORE POWER
C89  0.1uF  [c201-6p6spc]
C90  0.22uF  [c201-6p6spc]
C91  1uF  [c201-6p6spc]
C92  0.22uF  [c201-6p6spc]
C93  0.47uF  [c201-6p6spc]
C94  0.47uF  [c201-6p6spc]
C95  1uF  [c201-6p6spc]
C96  0.22uF  [c201-6p6spc]
C105  2.2uF  [c402-25]
C107  0.1uF  [c201-6p6spc]
C108  0.47uF  [c201-6p6spc]
C109  0.1uF  [c201-6p6spc]
C111  1uF  [c201-6p6spc]
C112  0.1uF  [c201-6p6spc]
C118  0.1uF  [c201-6p6spc]
C119  0.1uF  [c201-6p6spc]
C127  0.1uF  [c201-6p6spc]
C356  22uF  [c603-35x45]
C359  2.2uF  [c402-25]
C360  4.7uF  [c402-25]
C361  2.2uF  [c402-25]
C362  4.7uF  [c402-25]
C363  0.1uF  [c201-6p6spc]
C364  0.1uF  [c201-6p6spc]
C365  0.1uF  [c201-6p6spc]
C366  0.1uF  [c201-6p6spc]
C367  1uF  [c201-6p6spc]
C368  0.1uF  [c201-6p6spc]
C369  0.1uF  [c201-6p6spc]
C370  0.1uF  [c201-6p6spc]
C372  0.1uF  [c201-6p6spc]
C373  1uF  [c201-6p6spc]
C374  0.47uF  [c201-6p6spc]
C384  0.1uF  [c201-6p6spc]
C385  0.1uF  [c201-6p6spc]
C386  0.1uF  [c201-6p6spc]
C387  0.1uF  [c201-6p6spc]
C388  0.1uF  [c201-6p6spc]
C389  0.1uF  [c201-6p6spc]
C390  0.1uF  [c201-6p6spc]
C391  0.1uF  [c201-6p6spc]
C392  0.1uF  [c201-6p6spc]
C393  1uF  [c201-6p6spc]
C394  0.47uF  [c201-6p6spc]
C395  0.22uF  [c201-6p6spc]
C396  0.1uF  [c201-6p6spc]
C397  0.1uF  [c201-6p6spc]
C398  0.1uF  [c201-6p6spc]
C452  4.7uF  [c402-25]
C453  4.7uF  [c402-25]
C456  2.2uF  [c402-25]
C460  10uF  [c402-25]
C463  0.1uF  [c201-6p6spc]
C465  0.22uF  [c201-6p6spc]
C466  0.1uF  [c201-6p6spc]
C469  0.1uF  [c201-6p6spc]
C473  0.1uF  [c201-6p6spc]
C474  0.1uF  [c201-6p6spc]
C475  0.1uF  [c201-6p6spc]
C478  0.47uF  [c201-6p6spc]
C483  1uF  [c201-6p6spc]
C487  4.7uF  [c402-25]
C492  0.1uF  [c201-6p6spc]
C495  0.1uF  [c201-6p6spc]
C498  0.1uF  [c201-6p6spc]
C505  0.1uF  [c201-6p6spc]
sheet SH48 - DDR3 EMIF1 TESTPOINTS
TP1MA1  TP_VIA_MEM3  [tp1-18rd8]
TP1MA2  TP_VIA_MEM3  [tp1-18rd8]
TP1MA3  TP_VIA_MEM3  [tp1-18rd8]
TP1MA4  TP_VIA_MEM3  [tp1-18rd8]
TP1MA5  TP_VIA_MEM3  [tp1-18rd8]
TP1MA6  TP_VIA_MEM3  [tp1-18rd8]
TP1MA7  TP_VIA_MEM3  [tp1-18rd8]
TP1MA8  TP_VIA_MEM3  [tp1-18rd8]
TP1MA9  TP_VIA_MEM3  [tp1-18rd8]
TP1MA10  TP_VIA_MEM3  [tp1-18rd8]
TP1MA11  TP_VIA_MEM3  [tp1-18rd8]
TP1MA12  TP_VIA_MEM3  [tp1-18rd8]
TP1MA13  TP_VIA_MEM3  [tp1-18rd8]
TP1MA14  TP_VIA_MEM3  [tp1-18rd8]
TP1MA15  TP_VIA_MEM3  [tp1-18rd8]
TP1MA16  TP_VIA_MEM3  [tp1-18rd8]
TP1MA17  TP_VIA_MEM3  [tp1-18rd8]
TP1MA18  TP_VIA_MEM3  [tp1-18rd8]
TP1MA19  TP_VIA_MEM3  [tp1-18rd8]
TP1MA20  TP_VIA_MEM3  [tp1-18rd8]
TP1MA21  TP_VIA_MEM3  [tp1-18rd8]
TP1MA22  TP_VIA_MEM3  [tp1-18rd8]
TP1MA23  TP_VIA_MEM3  [tp1-18rd8]
TP1MA24  TP_VIA_MEM3  [tp1-18rd8]
TP1MA25  TP_VIA_MEM3  [tp1-18rd8]
TP1MA26  TP_VIA_MEM3  [tp1-18rd8]
TP1MA27  TP_VIA_MEM3  [tp1-18rd8]
TP1MB1  TP_VIA_MEM3  [tp1-18rd8]
TP1MB2  TP_VIA_MEM3  [tp1-18rd8]
TP1MB3  TP_VIA_MEM3  [tp1-18rd8]
TP1MB4  TP_VIA_MEM3  [tp1-18rd8]
TP1MB5  TP_VIA_MEM3  [tp1-18rd8]
TP1MB6  TP_VIA_MEM3  [tp1-18rd8]
TP1MB7  TP_VIA_MEM3  [tp1-18rd8]
TP1MB8  TP_VIA_MEM3  [tp1-18rd8]
TP1MB9  TP_VIA_MEM3  [tp1-18rd8]
TP1MB10  TP_VIA_MEM3  [tp1-18rd8]
TP1MB11  TP_VIA_MEM3  [tp1-18rd8]
TP1MB12  TP_VIA_MEM3  [tp1-18rd8]
TP1MB13  TP_VIA_MEM3  [tp1-18rd8]
TP1MB14  TP_VIA_MEM3  [tp1-18rd8]
TP1MB15  TP_VIA_MEM3  [tp1-18rd8]
TP1MB16  TP_VIA_MEM3  [tp1-18rd8]
TP1MB17  TP_VIA_MEM3  [tp1-18rd8]
TP1MB18  TP_VIA_MEM3  [tp1-18rd8]
TP1MB19  TP_VIA_MEM3  [tp1-18rd8]
TP1MB20  TP_VIA_MEM3  [tp1-18rd8]
TP1MB21  TP_VIA_MEM3  [tp1-18rd8]
TP1MB22  TP_VIA_MEM3  [tp1-18rd8]
TP1MB23  TP_VIA_MEM3  [tp1-18rd8]
TP1MB24  TP_VIA_MEM3  [tp1-18rd8]
TP1MB25  TP_VIA_MEM3  [tp1-18rd8]
TP1MB26  TP_VIA_MEM3  [tp1-18rd8]
TP1MB27  TP_VIA_MEM3  [tp1-18rd8]
TP1MC1  TP_VIA_MEM2  [tp1-18rd8]
TP1MC2  TP_VIA_MEM2  [tp1-18rd8]
TP1MC3  TP_VIA_MEM2  [tp1-18rd8]
TP1MC4  TP_VIA_MEM2  [tp1-18rd8]
TP1MC5  TP_VIA_MEM2  [tp1-18rd8]
TP1MC6  TP_VIA_MEM2  [tp1-18rd8]
TP1MC7  TP_VIA_MEM2  [tp1-18rd8]
TP1MC8  TP_VIA_MEM2  [tp1-18rd8]
TP1MC9  TP_VIA_MEM2  [tp1-18rd8]
TP1MC10  TP_VIA_MEM2  [tp1-18rd8]
TP1MC11  TP_VIA_MEM2  [tp1-18rd8]
TP1MC12  TP_VIA_MEM2  [tp1-18rd8]
TP1MC13  TP_VIA_MEM2  [tp1-18rd8]
TP1MC14  TP_VIA_MEM2  [tp1-18rd8]
TP1MC15  TP_VIA_MEM2  [tp1-18rd8]
TP1MC16  TP_VIA_MEM2  [tp1-18rd8]
TP1MC17  TP_VIA_MEM2  [tp1-18rd8]
TP1MC18  TP_VIA_MEM2  [tp1-18rd8]
TP1MC19  TP_VIA_MEM2  [tp1-18rd8]
TP1MC20  TP_VIA_MEM2  [tp1-18rd8]
TP1MC21  TP_VIA_MEM2  [tp1-18rd8]
TP1MC22  TP_VIA_MEM2  [tp1-18rd8]
TP1MC23  TP_VIA_MEM2  [tp1-18rd8]
TP1MC24  TP_VIA_MEM2  [tp1-18rd8]
TP1MC25  TP_VIA_MEM2  [tp1-18rd8]
TP1MC26  TP_VIA_MEM2  [tp1-18rd8]
TP2MC1  TP_VIA_MEM2  [tp1-18rd8]
sheet SH49 - DDR3  BANK 1
C203  0.22uF  [c201-6p6spc]
C204  0.22uF  [c201-6p6spc]
C205  0.22uF  [c201-6p6spc]
C617  0.22uF  [c201-6p6spc]
C618  0.22uF  [c201-6p6spc]
C619  0.22uF  [c201-6p6spc]
R691  240  [r402-25]
R692  240  [r402-25]
R693  240  [r402-25]
R804  4.7K  [r402-25]
U65  MT41K512M16HA-125 AIT:A (IT)  [bga6x16-p8-re-pkg]
U66  MT41K512M16HA-125 AIT:A (IT)  [bga6x16-p8-re-pkg]
U67  MT41K512M8RH-125-AAT:E (IT)  [bga6x13-p8-ra-pkg]
sheet SH50 - DDR3 EMIF1 CAPS
C182  0.22uF  [c201-6p6spc]
C183  0.22uF  [c201-6p6spc]
C193  0.22uF  [c201-6p6spc]
C194  0.22uF  [c201-6p6spc]
C210  10uF  [c603-35x45]
C211  10uF  [c603-35x45]
C212  10uF  [c603-35x45]
C213  10uF  [c603-35x45]
C214  10uF  [c603-35x45]
C580  0.22uF  [c201-6p6spc]
C583  0.22uF  [c201-6p6spc]
C587  0.22uF  [c201-6p6spc]
C588  0.22uF  [c201-6p6spc]
C590  0.22uF  [c201-6p6spc]
C591  0.22uF  [c201-6p6spc]
C594  0.22uF  [c201-6p6spc]
C597  0.22uF  [c201-6p6spc]
C598  0.22uF  [c201-6p6spc]
C600  0.22uF  [c201-6p6spc]
C602  0.22uF  [c201-6p6spc]
C603  0.22uF  [c201-6p6spc]
C605  0.22uF  [c201-6p6spc]
C606  0.22uF  [c201-6p6spc]
C608  0.22uF  [c201-6p6spc]
C609  0.22uF  [c201-6p6spc]
C610  0.22uF  [c201-6p6spc]
C611  0.22uF  [c201-6p6spc]
C612  0.22uF  [c201-6p6spc]
C613  0.22uF  [c201-6p6spc]
C614  0.22uF  [c201-6p6spc]
C621  0.22uF  [c201-6p6spc]
C622  0.22uF  [c201-6p6spc]
C623  0.22uF  [c201-6p6spc]
C624  0.22uF  [c201-6p6spc]
C625  0.22uF  [c201-6p6spc]
C632  0.22uF  [c201-6p6spc]
C633  0.22uF  [c201-6p6spc]
C638  0.22uF  [c201-6p6spc]
C639  0.22uF  [c201-6p6spc]
C640  0.22uF  [c201-6p6spc]
C641  0.22uF  [c201-6p6spc]
sheet SH51 - DDR3 BANK1 TERMINATION
C164  0.22uF  [c402-25]
C165  0.22uF  [c402-25]
C175  0.22uF  [c402-25]
C180  0.22uF  [c402-25]
C206  0.22uF  [c402-25]
C207  0.22uF  [c402-25]
C599  0.1uF  [c402-25]
C627  0.22uF  [c402-25]
C635  0.22uF  [c402-25]
C643  0.22uF  [c402-25]
C654  0.22uF  [c402-25]
C662  0.22uF  [c402-25]
C663  0.22uF  [c402-25]
R684  49.9/1%  [r402-25]
R687  49.9/1%  [r402-25]
R689  49.9-1%  [r402-25]
RN2  R-PACK4-47  [rpak8-10x25-28v]
RN4  R-PACK4-47  [rpak8-10x25-28v]
RN6  R-PACK4-47  [rpak8-10x25-28v]
RN13  R-PACK4-47  [rpak8-10x25-28v]
RN15  R-PACK4-47  [rpak8-10x25-28v]
RN17  R-PACK4-47  [rpak8-10x25-28v]
sheet SH52 - TESTPOINTS DDR3  EMIF 2
TP2MA1  TP_VIA_MEM0  [tp1-18rd8]
TP2MA2  TP_VIA_MEM0  [tp1-18rd8]
TP2MA3  TP_VIA_MEM0  [tp1-18rd8]
TP2MA4  TP_VIA_MEM0  [tp1-18rd8]
TP2MA5  TP_VIA_MEM0  [tp1-18rd8]
TP2MA6  TP_VIA_MEM0  [tp1-18rd8]
TP2MA7  TP_VIA_MEM0  [tp1-18rd8]
TP2MA8  TP_VIA_MEM0  [tp1-18rd8]
TP2MA9  TP_VIA_MEM0  [tp1-18rd8]
TP2MA10  TP_VIA_MEM0  [tp1-18rd8]
TP2MA11  TP_VIA_MEM0  [tp1-18rd8]
TP2MA12  TP_VIA_MEM0  [tp1-18rd8]
TP2MA13  TP_VIA_MEM0  [tp1-18rd8]
TP2MA14  TP_VIA_MEM0  [tp1-18rd8]
TP2MA15  TP_VIA_MEM0  [tp1-18rd8]
TP2MA16  TP_VIA_MEM0  [tp1-18rd8]
TP2MA17  TP_VIA_MEM0  [tp1-18rd8]
TP2MA18  TP_VIA_MEM0  [tp1-18rd8]
TP2MA19  TP_VIA_MEM0  [tp1-18rd8]
TP2MA20  TP_VIA_MEM0  [tp1-18rd8]
TP2MA21  TP_VIA_MEM0  [tp1-18rd8]
TP2MA22  TP_VIA_MEM0  [tp1-18rd8]
TP2MA23  TP_VIA_MEM0  [tp1-18rd8]
TP2MA24  TP_VIA_MEM0  [tp1-18rd8]
TP2MA25  TP_VIA_MEM0  [tp1-18rd8]
TP2MA26  TP_VIA_MEM0  [tp1-18rd8]
TP2MA27  TP_VIA_MEM0  [tp1-18rd8]
TP2MB1  TP_VIA_MEM1  [tp1-18rd8]
TP2MB2  TP_VIA_MEM1  [tp1-18rd8]
TP2MB3  TP_VIA_MEM1  [tp1-18rd8]
TP2MB4  TP_VIA_MEM1  [tp1-18rd8]
TP2MB5  TP_VIA_MEM1  [tp1-18rd8]
TP2MB6  TP_VIA_MEM1  [tp1-18rd8]
TP2MB7  TP_VIA_MEM1  [tp1-18rd8]
TP2MB8  TP_VIA_MEM1  [tp1-18rd8]
TP2MB9  TP_VIA_MEM1  [tp1-18rd8]
TP2MB10  TP_VIA_MEM1  [tp1-18rd8]
TP2MB11  TP_VIA_MEM1  [tp1-18rd8]
TP2MB12  TP_VIA_MEM1  [tp1-18rd8]
TP2MB13  TP_VIA_MEM1  [tp1-18rd8]
TP2MB14  TP_VIA_MEM1  [tp1-18rd8]
TP2MB15  TP_VIA_MEM1  [tp1-18rd8]
TP2MB16  TP_VIA_MEM1  [tp1-18rd8]
TP2MB17  TP_VIA_MEM1  [tp1-18rd8]
TP2MB18  TP_VIA_MEM1  [tp1-18rd8]
TP2MB19  TP_VIA_MEM1  [tp1-18rd8]
TP2MB20  TP_VIA_MEM1  [tp1-18rd8]
TP2MB21  TP_VIA_MEM1  [tp1-18rd8]
TP2MB22  TP_VIA_MEM1  [tp1-18rd8]
TP2MB23  TP_VIA_MEM1  [tp1-18rd8]
TP2MB24  TP_VIA_MEM1  [tp1-18rd8]
TP2MB25  TP_VIA_MEM1  [tp1-18rd8]
TP2MB26  TP_VIA_MEM1  [tp1-18rd8]
TP2MB27  TP_VIA_MEM1  [tp1-18rd8]
sheet SH53 - DDR3 MEMORY BANK 2
C177  0.22uF  [c201-6p6spc]
C178  0.22uF  [c201-6p6spc]
C197  0.22uF  [c201-6p6spc]
C198  0.22uF  [c201-6p6spc]
C628  0.22uF  [c201-6p6spc]
C629  0.22uF  [c201-6p6spc]
C651  0.22uF  [c201-6p6spc]
C652  0.22uF  [c201-6p6spc]
R288  240  [r402-25]
R289  240  [r402-25]
R694  240  [r402-25]
R695  240  [r402-25]
R805  4.7K  [r402-25]
U68  MT41K512M8RH-125-AAT:E  (IT)  [bga6x13-p8-ra-pkg]
U69  MT41K512M8RH-125-AAT:E  (IT)  [bga6x13-p8-ra-pkg]
U115  MT41K512M8RH-125-AAT:E  (IT)  [bga6x13-p8-ra-pkg]
U116  MT41K512M8RH-125-AAT:E  (IT)  [bga6x13-p8-ra-pkg]

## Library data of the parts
U52 = VAYU_DEC_3_2: Part #: 104183-0003R
C104 C210-C214 C355 C357 C382 C406 C436 C493 = CAP: Part #: 102963-0101R
C363 C364 C368 C370 C386 C388 C390-C392 C399 C400 C412 C414 C415 C437 C444 C450 C455 C458 C461 C498 C507 C518 C542 = NPCap_0: Part #: 103241-1100R
C89 C107 C109 C112 C118 C119 C127 C365 C366 C369 C371 C372 C384 C385 C387 C389 C396-C398 C401 C402 C438 C442 C443 C445 C449 C454 C457 C463 C464 C466 C467 C469 C471 C473-C475 C482 C484 C492 C494-C496 C500 C502 C505 C524 C526 C530 C545 C699 C700 = CAP_NP: Part #: 103241-1100R
R799 = R: Part #: r0402-nopop
R800 = R: Part #: 101370-0001R
R801 = R: Part #: 101370-1502R
U136 = tps2115a: Part #: 104415-0001R
TP51 = TestPoint1_0: Part #: TP-18RD8-NO-POP
C136 C548 C556 C557 C560 C561 C564 C571 C580 C609 = CAP: Part #: 103214-1220R
C137-C139 C143 C148 C508 C528 C537 C541 C549 C559 C563 C570 C574 C578 C584 = CAP: Part #: 103241-1100R
C140 C356 C562 = CAP: Part #: 103911-0221R
C569 C576 C655 C656 = CAP: Part #: 102962-0100R
C572 C577 C589 C657 = CAP: Part #: 103649-0470R
C413 C420 C422 C491 = CAP_NP_0: Part #: 103241-1101R
C418 C426 C429 C490 = CAP_NP_0: Part #: 103214-0100R
C419 C425 C427 C497 = CAP_NP_0: Part #: 103367-1102R
E3-E6 = NFM_1: Part #: 102569-1470R
C90 C92 C96 C395 C465 = NPCap_0: Part #: 103214-1220R
C91 C95 C111 C367 C373 C393 C483 = NPCap_0: Part #: 103214-0100R
C93 C94 C108 C374 C394 C478 = NPCap_0: Part #: 104275-1470R
C105 C359 C361 C456 = NPCap_0: Part #: 103649-0220R
C360 C362 C452 C453 C487 = NPCap_0: Part #: 103649-0470R
C460 = CAP: Part #: 104300-0101R
TP1MA1-TP1MA27 TP1MB1-TP1MB27 = TP_VIA_MEM3_0: Part #: TP-18RD8-NO-POP
TP1MC1-TP1MC26 TP2MC1 = TP_VIA_MEM2_0: Part #: TP-18RD8-NO-POP
C182 C183 C193 C203 C204 C583 C588 C591 C594 C597 C598 C600 C602 C603 C605 C606 C610-C614 C618 C619 C621-C625 C632 C633 C638-C641 = CAP_NP_0: Part #: 103214-1220R; SD PCB Footprint: EIA0402
C177 C178 C194 C197 C198 C205 C587 C590 C608 C617 C628 C629 C651 C652 = CAP_NP_0: Part #: 103214-1220R
R691 R692 = R_0: Part #: 101370-2401R; SD PCB Footprint: EIA0402
R288 R289 R693-R695 = R: Part #: 101370-2401R
R804 R805 = R: Part #: 101370-4702R
U65 U66 = DDR3_96BALL_X16_0: Part #: 104694-0125R
U67-U69 U115 U116 = EDJ1108DBSE_1: Part #: 104695-0125R
C164 C165 C175 C180 C206 C207 C627 C635 C643 C654 C662 C663 = CAP_NP_0: Part #: 101587-1220R; SD PCB Footprint: EIA0402
C599 = SC10N16V2KX_0: @CAP SMD 0402 10nf 16V ??10% X7R; Part #: 101587-1100R
R684 R687 = 1KR2F: @RES SMD 0402 1K·[ ??1% 1/16W; Part #: 102145-4990R
R689 = R: Part #: 102145-4990R
RN2 RN4 RN6 RN13 RN15 RN17 = R-Pak4_0: Part #: 101327-4700R
TP2MA1-TP2MA27 = TP_VIA_MEM0_0: Part #: TP-18RD8-NO-POP
TP2MB1-TP2MB27 = TP_VIA_MEM1_0: Part #: TP-18RD8-NO-POP

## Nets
GND: C89.2 C90.1 C91.1 C92.1 C93.1 C94.1 C95.1 C96.1 C104.2 C105.1 C107.2 C108.1 C109.2 C111.1 C112.2 C118.2 C119.2 C127.2 C136.2 C137.2 C138.2 C139.2 C140.2 C143.2 C148.2 C177.2 C178.2 C182.2 C183.2 C193.2 C194.2 C210.2 C211.2 C212.2 C213.2 C214.2 C355.2 C356.2 C357.2 C359.1 C360.1 C361.1 C362.1 C363.1 C364.1 C365.2 C366.2 C367.1 C368.1 C369.2 C370.1 C371.2 C372.2 C373.1 C374.1 C382.2 C384.2 C385.2 C386.1 C387.2 C388.1 C389.2 C390.1 C391.1 C392.1 C393.1 C394.1 C395.1 C396.2 C397.2 C398.2 C399.1 C400.1 C401.2 C402.2 C406.2 C412.1 C413.2 C414.1 C415.1 C418.2 C419.2 C420.2 C422.2 C425.2 C426.2 C427.2 C429.2 C436.2 C437.1 C438.2 C442.2 C443.2 C444.1 C445.2 C449.2 C450.1 C452.1 C453.1 C454.2 C455.1 C456.1 C457.2 C458.1 C460.2 C461.1 C463.2 C464.2 C465.1 C466.2 C467.2 C469.2 C471.2 C473.2 C474.2 C475.2 C478.1 C482.2 C483.1 C484.2 C487.1 C490.2 C491.2 C492.2 C493.2 C494.2 C495.2 C496.2 C497.2 C498.1 C500.2 C502.2 C505.2 C507.1 C508.2 C518.1 C524.2 C526.2 C528.2 C530.2 C537.2 C541.2 C542.1 C545.2 C548.2 C549.2 C556.2 C557.2 C559.2 C560.2 C561.2 C562.2 C563.2 C564.2 C569.2 C570.2 C571.2 C572.2 C574.2 C576.2 C577.2 C578.2 C580.2 C583.2 C584.2 C587.2 C588.2 C589.2 C590.2 C591.2 C594.2 C597.2 C598.2 C600.2 C602.2 C603.2 C605.2 C606.2 C608.2 C609.2 C610.2 C611.2 C612.2 C613.2 C614.2 C617.2 C618.2 C619.2 C621.2 C622.2 C623.2 C624.2 C625.2 C628.2 C629.2 C632.2 C633.2 C638.2 C639.2 C640.2 C641.2 C655.2 C656.2 C657.2 C699.2 C700.2 E3.2 E4.2 E5.2 E6.2 R288.2 R289.2 R691.2 R692.2 R693.2 R694.2 R695.2 R801.1 R804.2 R805.2 U52.A1(VSS.9) U52.A2(VSS.11) U52.A6(VSS.15) U52.A14(VSS.41) U52.A23(VSS.68) U52.A28(VSS.79) U52.AA8(VSS.17) U52.AA9(VSS.19) U52.AA10(VSS.14) U52.AA14(VSS.48) U52.AA15(VSS.51) U52.AA20(VSS.61) U52.AB14(VSS.40) U52.AB20(VSS.60) U52.AD1(VSS.3) U52.AD24(VSS.70) U52.AG1(VSS.2) U52.AH1(VSS.1) U52.AH2(VSS.10) U52.AH8(VSS.53) U52.AH20(VSS.52) U52.AH28(VSS.75) U52.B1(VSS.8) U52.D13(VSS.39) U52.D19(VSS.59) U52.E13(VSS.38) U52.E19(VSS.58) U52.F1(VSS.7) U52.F7(VSS.54) U52.G7(VSS.57) U52.G8(VSS.65) U52.G9(VSS.66) U52.H12(VSS.33) U52.J12(VSS.32) U52.J15(VSS.XX) U52.J28(VSS.78) U52.K1(VSS.6) U52.K4(VSS.12) U52.K5(VSS.13) U52.K15(VSS.28) U52.K24(VSS.55) U52.K25(VSS.56) U52.L13(VSS.37) U52.L14(VSS.46) U52.M19(VSS.69) U52.N14(VSS.X5) U52.N15(VSS.16) U52.N19(VSS.18) U52.N24(VSS.72) U52.N25(VSS.74) U52.P28(VSS.77) U52.R1(VSS.5) U52.R12(VSS.29) U52.R13(VSS.X6) U52.R15(VSS.43) U52.R21(VSS.64) U52.T10(VSS.21) U52.T11(VSS.26) U52.T12(VSS.23) U52.T14(VSS.X7) U52.T15(VSS.42) U52.T17(VSS.47) U52.T18(VSS.24) U52.T21(VSS.27) U52.U14(VSSA_VIDEO) U52.U15(VSS.X8) U52.U17(VSS.X9) U52.U20(VSS.62) U52.U21(VSS.63) U52.V15(VSS.30) U52.V17(VSS.X10) U52.W1(VSS.4) U52.W15(VSS.36) U52.W24(VSS.71) U52.W25(VSS.73) U52.W28(VSS.76) U65.A9(VSS.1) U65.B1(VSSQ.1) U65.B3(VSS.2) U65.B9(VSSQ.2) U65.D1(VSSQ.3) U65.D8(VSSQ.4) U65.E1(VSS.3) U65.E2(VSSQ.5) U65.E8(VSSQ.6) U65.F9(VSSQ.7) U65.G1(VSSQ.8) U65.G8(VSS.4) U65.G9(VSSQ.9) U65.J2(VSSDL) U65.J8(VSS.5) U65.M1(VSS.6) U65.M9(VSS.7) U65.P1(VSS.8) U65.P9(VSS.9) U65.T1(VSS.10) U65.T9(VSS.11) U66.A9(VSS.1) U66.B1(VSSQ.1) U66.B3(VSS.2) U66.B9(VSSQ.2) U66.D1(VSSQ.3) U66.D8(VSSQ.4) U66.E1(VSS.3) U66.E2(VSSQ.5) U66.E8(VSSQ.6) U66.F9(VSSQ.7) U66.G1(VSSQ.8) U66.G8(VSS.4) U66.G9(VSSQ.9) U66.J2(VSSDL) U66.J8(VSS.5) U66.M1(VSS.6) U66.M9(VSS.7) U66.P1(VSS.8) U66.P9(VSS.9) U66.T1(VSS.10) U66.T9(VSS.11) U67.A1(VSS.1) U67.A8(VSS.2) U67.B1(VSS.3) U67.B2(VSSQ) U67.B8(VSSQ) U67.C9(VSSQ) U67.D1(VSSQ) U67.D8(VSS.4) U67.D9(VSSQ) U67.F2(VSS.5) U67.F8(VSS.6) U67.J1(VSS.7) U67.J9(VSS.8) U67.L1(VSS.9) U67.L9(VSS.10) U67.N1(VSS.11) U67.N9(VSS.12) U68.A1(VSS.1) U68.A8(VSS.2) U68.B1(VSS.3) U68.B2(VSSQ) U68.B8(VSSQ) U68.C9(VSSQ) U68.D1(VSSQ) U68.D8(VSS.4) U68.D9(VSSQ) U68.F2(VSS.5) U68.F8(VSS.6) U68.J1(VSS.7) U68.J9(VSS.8) U68.L1(VSS.9) U68.L9(VSS.10) U68.N1(VSS.11) U68.N9(VSS.12) U69.A1(VSS.1) U69.A8(VSS.2) U69.B1(VSS.3) U69.B2(VSSQ) U69.B8(VSSQ) U69.C9(VSSQ) U69.D1(VSSQ) U69.D8(VSS.4) U69.D9(VSSQ) U69.F2(VSS.5) U69.F8(VSS.6) U69.J1(VSS.7) U69.J9(VSS.8) U69.L1(VSS.9) U69.L9(VSS.10) U69.N1(VSS.11) U69.N9(VSS.12) U115.A1(VSS.1) U115.A8(VSS.2) U115.B1(VSS.3) U115.B2(VSSQ) U115.B8(VSSQ) U115.C9(VSSQ) U115.D1(VSSQ) U115.D8(VSS.4) U115.D9(VSSQ) U115.F2(VSS.5) U115.F8(VSS.6) U115.J1(VSS.7) U115.J9(VSS.8) U115.L1(VSS.9) U115.L9(VSS.10) U115.N1(VSS.11) U115.N9(VSS.12) U116.A1(VSS.1) U116.A8(VSS.2) U116.B1(VSS.3) U116.B2(VSSQ) U116.B8(VSSQ) U116.C9(VSSQ) U116.D1(VSSQ) U116.D8(VSS.4) U116.D9(VSSQ) U116.F2(VSS.5) U116.F8(VSS.6) U116.J1(VSS.7) U116.J9(VSS.8) U116.L1(VSS.9) U116.L9(VSS.10) U116.N1(VSS.11) U116.N9(VSS.12) U136.2(D0) U136.5(GND) U136.PAD ; also on sheet 3 4 5 7 8 9 10 11 13 15 16 17 18 19 20 21 24 25 26 27 28 29 30 31 32 33 34 47 49 50 51 52 53 54 55 56 57 58 60 61 62 63 64 65 66 67 68 69 70 71 72 73 74 75 77 79 80 81 84 85 86 87 88 89
VDD_DDR: C164.2 C165.2 C175.2 C180.2 C182.1 C183.1 C193.1 C194.1 C197.2 C198.2 C203.2 C204.2 C205.2 C206.2 C207.2 C210.1 C211.1 C212.1 C213.1 C214.1 C580.1 C583.1 C587.1 C588.1 C590.1 C591.1 C594.1 C597.1 C598.1 C599.2 C600.1 C602.1 C603.1 C605.1 C606.1 C608.1 C609.1 C610.1 C611.1 C612.1 C613.1 C614.1 C621.1 C622.1 C623.1 C624.1 C625.1 C627.2 C632.1 C633.1 C635.2 C638.1 C639.1 C640.1 C641.1 C643.2 C651.2 C652.2 C654.2 C662.2 C663.2 U65.A1(VDDQ.1) U65.A8(VDDQ.2) U65.B2(VDD.1) U65.C1(VDDQ.3) U65.C9(VDDQ.4) U65.D2(VDDQ.5) U65.D9(VDD.2) U65.E9(VDDQ.6) U65.F1(VDDQ.7) U65.G7(VDD.3) U65.H2(VDDQ.8) U65.H9(VDDQ.9) U65.K2(VDDL) U65.K8(VDD.4) U65.N1(VDD.5) U65.N9(VDD.6) U65.R1(VDD.7) U65.R9(VDD.8) U66.A1(VDDQ.1) U66.A8(VDDQ.2) U66.B2(VDD.1) U66.C1(VDDQ.3) U66.C9(VDDQ.4) U66.D2(VDDQ.5) U66.D9(VDD.2) U66.E9(VDDQ.6) U66.F1(VDDQ.7) U66.G7(VDD.3) U66.H2(VDDQ.8) U66.H9(VDDQ.9) U66.K2(VDDL) U66.K8(VDD.4) U66.N1(VDD.5) U66.N9(VDD.6) U66.R1(VDD.7) U66.R9(VDD.8) U67.A2(VDD.1) U67.A9(VDD.2) U67.B9(VDDQ.1) U67.C1(VDDQ.2) U67.D7(VDD.3) U67.E2(VDDQ.3) U67.E9(VDDQ.4) U67.G2(VDD.4) U67.G8(VDD.5) U67.K1(VDD.6) U67.K9(VDD.7) U67.M1(VDD.8) U67.M9(VDD.9) U68.A2(VDD.1) U68.A9(VDD.2) U68.B9(VDDQ.1) U68.C1(VDDQ.2) U68.D7(VDD.3) U68.E2(VDDQ.3) U68.E9(VDDQ.4) U68.G2(VDD.4) U68.G8(VDD.5) U68.K1(VDD.6) U68.K9(VDD.7) U68.M1(VDD.8) U68.M9(VDD.9) U69.A2(VDD.1) U69.A9(VDD.2) U69.B9(VDDQ.1) U69.C1(VDDQ.2) U69.D7(VDD.3) U69.E2(VDDQ.3) U69.E9(VDDQ.4) U69.G2(VDD.4) U69.G8(VDD.5) U69.K1(VDD.6) U69.K9(VDD.7) U69.M1(VDD.8) U69.M9(VDD.9) U115.A2(VDD.1) U115.A9(VDD.2) U115.B9(VDDQ.1) U115.C1(VDDQ.2) U115.D7(VDD.3) U115.E2(VDDQ.3) U115.E9(VDDQ.4) U115.G2(VDD.4) U115.G8(VDD.5) U115.K1(VDD.6) U115.K9(VDD.7) U115.M1(VDD.8) U115.M9(VDD.9) U116.A2(VDD.1) U116.A9(VDD.2) U116.B9(VDDQ.1) U116.C1(VDDQ.2) U116.D7(VDD.3) U116.E2(VDDQ.3) U116.E9(VDDQ.4) U116.G2(VDD.4) U116.G8(VDD.5) U116.K1(VDD.6) U116.K9(VDD.7) U116.M1(VDD.8) U116.M9(VDD.9) ; also on sheet 47 48 73 81
VDD_DSPEVE: C105.2 C108.2 C109.1 C111.2 C112.1 C118.1 C119.1 C453.2 C460.1 C465.2 C466.1 C473.1 C474.1 C483.2 C495.1 U52.J13(VDD_DSPEVE.7) U52.K10(VDD_DSPEVE.8) U52.K11(VDD_DSPEVE.9) U52.K12(VDD_DSPEVE.10) U52.K13(VDD_DSPEVE.11) U52.L10(VDD_DSPEVE.2) U52.L11(VDD_DSPEVE.4) U52.L12(VDD_DSPEVE.12) U52.M10(VDD_DSPEVE.1) U52.M11(VDD_DSPEVE.5) U52.M12(VDD_DSPEVE.3) U52.M13(VDD_DSPEVE.6) ; also on sheet 65 72 81
VDD_GPU: C89.1 C90.2 C361.2 C362.2 C372.1 C373.2 C374.2 C397.1 C398.1 C469.1 C475.1 U52.U11(VDD_GPU.5) U52.U12(VDD_GPU.6) U52.V10(VDD_GPU.2) U52.V11(VDD_GPU.3) U52.V14(VDD_GPU.7) U52.W10(VDD_GPU.1) U52.W11(VDD_GPU.4) U52.W13(VDD_GPU.8) ; also on sheet 66 72 81
VDD_IVA: C107.1 C127.1 C452.2 C463.1 C478.2 C492.1 C505.1 U52.U18(VDD_IVA.1) U52.U19(VDD_IVA.2) U52.V18(VDD_IVA.3) U52.V19(VDD_IVA.4) ; also on sheet 66 72 81
VDD_MPU: C91.2 C92.2 C93.2 C94.2 C95.2 C96.2 C356.1 C359.2 C360.2 C365.1 C366.1 C367.2 C368.2 C369.1 C370.2 C384.1 C385.1 C387.1 C389.1 C391.2 C392.2 C396.1 U52.K17(VDD_MPU.10) U52.K18(VDD_MPU.2) U52.L15(VDD_MPU.11) U52.L16(VDD_MPU.12) U52.L17(VDD_MPU.6) U52.L18(VDD_MPU.8) U52.L19(VDD_MPU.3) U52.M15(VDD_MPU.13) U52.M16(VDD_MPU.14) U52.M17(VDD_MPU.5) U52.M18(VDD_MPU.7) U52.N17(VDD_MPU.4) U52.N18(VDD_MPU.1) U52.P17(VDD_MPU.15) U52.P18(VDD_MPU.9) U52.R18(VDD_MPU.16) ; also on sheet 65 72 79 81
VDDA_1V8_PLL: E3.3 E4.3 E5.3 E6.3 ; also on sheet 33 75
VDDS18V: C357.1 C371.1 C382.1 C399.2 C400.2 C401.1 C402.1 C406.1 C461.2 C471.1 C518.2 C524.1 C530.1 R800.2 U52.AA18(VDDS18V_DDR1.1) U52.AA19(VDDS18V_DDR1.2) U52.G18(VDDS18V.8) U52.H17(VDDS18V.11) U52.J21(VDDS18V_DDR2.3) U52.J22(VDDS18V_DDR2.4) U52.M8(VDDS18V.9) U52.M9(VDDS18V.7) U52.N8(VDDS18V.4) U52.N21(VDDS18V_DDR2.2) U52.P8(VDDS18V.5) U52.P20(VDDS18V_DDR2.5) U52.P21(VDDS18V_DDR2.1) U52.R8(VDDS18V.3) U52.T8(VDDS18V.2) U52.V21(VDDS18V.12) U52.V22(VDDS18V.6) U52.W17(VDDS18V.10) U52.W18(VDDS18V.1) U52.W21(VDDS18V_DDR1.4) U52.Y21(VDDS18V_DDR1.3) ; also on sheet 11 66 74
VDDSHV: C104.1 C355.1 C436.1 C437.2 C438.1 C442.1 C443.1 C444.2 C445.1 C449.1 C450.2 C454.1 C455.2 C457.1 C464.1 C482.1 C484.1 C493.1 C494.1 C496.1 C500.1 C502.1 C526.1 C542.2 C545.1 C700.1 R799.2 U52.AB6(VDDSHV7.1) U52.AB7(VDDSHV7.2) U52.AD5(VDDSHV6.2) U52.AD7(VDDSHV6.4) U52.AE7(VDDSHV6.3) U52.AF5(VDDSHV6.1) U52.B6(VDDSHV2.1) U52.B23(VDDSHV3.9) U52.C24(VDDSHV4.1) U52.D10(VDDSHV2.5) U52.D16(VDDSHV3.4) U52.D22(VDDSHV3.8) U52.E3(VDDSHV1.1) U52.E5(VDDSHV1.4) U52.E10(VDDSHV2.4) U52.E16(VDDSHV3.3) U52.E22(VDDSHV3.7) U52.G4(VDDSHV1.2) U52.G5(VDDSHV1.3) U52.G15(VDDSHV3.2) U52.H8(VDDSHV1.5) U52.H9(VDDSHV1.6) U52.H10(VDDSHV2.2) U52.H11(VDDSHV2.3) U52.H15(VDDSHV3.1) U52.H16(VDDSHV3.6) U52.H18(VDDSHV3.5) U52.H19(VDDSHV3.10) U52.N4(VDDSHV10.2) U52.N5(VDDSHV10.4) U52.P10(VDDSHV10.6) U52.R7(VDDSHV10.5) U52.R10(VDDSHV10.7) U52.T4(VDDSHV10.1) U52.T5(VDDSHV10.3) U52.U10(VDDSHV9.3) U52.W4(VDDSHV9.1) U52.W5(VDDSHV9.2) U136.8(IN1) ; also on sheet 77 81
VDDSHV8: C467.1 U52.W8(VDDSHV8.2) U52.Y8(VDDSHV8.1) ; also on sheet 78
VDDSHV11: C458.2 R799.1 U52.J8(VDDSHV11.2) U52.K8(VDDSHV11.1) U136.7(OUT)
CORE_VDD: C363.2 C364.2 C386.2 C388.2 C390.2 C393.2 C394.2 C395.2 C456.2 C487.2 C498.2 U52.H13(VDD.18) U52.H14(VDD.22) U52.J17(VDD.X1) U52.J18(VDD.X2) U52.L7(VDD.34) U52.L8(VDD.15) U52.N10(VDD.6) U52.N13(VDD.16) U52.P11(VDD.9) U52.P12(VDD.12) U52.P13(VDD.X3) U52.R11(VDD.8) U52.R16(VDD.26) U52.R19(VDD.27) U52.T13(VDD.13) U52.T16(VDD.25) U52.T19(VDD.X7) U52.U8(VDD.29) U52.U9(VDD.2) U52.U13(VDD.3) U52.U16(VDD.X8) U52.V8(VDD.1) U52.V16(VDD.X9) ; also on sheet 66 72 81
CPU_VDD_DDR: C136.1 C137.1 C138.1 C139.1 C140.1 C143.1 C148.1 C508.1 C528.1 C537.1 C541.1 C548.1 C549.1 C556.1 C557.1 C559.1 C560.1 C561.1 C562.1 C563.1 C564.1 C569.1 C570.1 C571.1 C572.1 C574.1 C576.1 C577.1 C578.1 C584.1 C589.1 C655.1 C656.1 C657.1 U52.AA21(VDDS_DDR1.4) U52.AA22(VDDS_DDR1.2) U52.AB21(VDDS_DDR1.3) U52.AB22(VDDS_DDR1.7) U52.AB24(VDDS_DDR1.10) U52.AB25(VDDS_DDR1.11) U52.AC22(VDDS_DDR1.6) U52.AD26(VDDS_DDR1.12) U52.AG20(VDDS_DDR1.9) U52.AG28(VDDS_DDR1.5) U52.AH27(VDDS_DDR1.13) U52.E24(VDDS_DDR2.9) U52.G22(VDDS_DDR2.5) U52.G23(VDDS_DDR2.6) U52.H20(VDDS_DDR2.1) U52.H21(VDDS_DDR2.11) U52.H22(VDDS_DDR2.4) U52.J27(VDDS_DDR2.12) U52.L20(VDDS_DDR2.8) U52.L21(VDDS_DDR2.3) U52.M20(VDDS_DDR2.13) U52.M21(VDDS_DDR2.2) U52.T24(VDDS_DDR2.7) U52.T25(VDDS_DDR2.10) U52.W16(VDDS_DDR1.1) U52.W27(VDDS_DDR1.8) ; also on sheet 19 20 73
DDR1_A0: RN4.1(R1A) TP1MA19.1 TP1MB19.1 TP1MC14.1 U65.N3(A0) U66.N3(A0) U67.K3(A0) ; also on sheet 19
DDR1_A1: RN4.2(R2A) TP1MA20.1 TP1MB20.1 TP1MC16.1 U65.P7(A1) U66.P7(A1) U67.L7(A1) ; also on sheet 19
DDR1_A2: RN6.4(R4A) TP1MA27.1 TP1MB27.1 TP1MC26.1 U65.P3(A2) U66.P3(A2) U67.L3(A2) ; also on sheet 19
DDR1_A3: RN15.4(R4A) TP1MA14.1 TP1MB14.1 TP1MC13.1 U65.N2(A3) U66.N2(A3) U67.K2(A3) ; also on sheet 19
DDR1_A4: RN4.3(R3A) TP1MA16.1 TP1MB16.1 TP1MC17.1 U65.P8(A4) U66.P8(A4) U67.L8(A4) ; also on sheet 19
DDR1_A5: RN4.4(R4A) TP1MA21.1 TP1MB21.1 TP1MC18.1 U65.P2(A5) U66.P2(A5) U67.L2(A5) ; also on sheet 19
DDR1_A6: RN17.3(R3A) TP1MA22.1 TP1MB22.1 TP1MC21.1 U65.R8(A6) U66.R8(A6) U67.M8(A6) ; also on sheet 19
DDR1_A7: RN6.2(R2A) TP1MA17.1 TP1MB17.1 TP1MC22.1 U65.R2(A7) U66.R2(A7) U67.M2(A7) ; also on sheet 19
DDR1_A8: RN17.1(R1A) TP1MA26.1 TP1MB26.1 TP1MC25.1 U65.T8(A8) U66.T8(A8) U67.N8(A8) ; also on sheet 19
DDR1_A9: RN6.1(R1A) TP1MA25.1 TP1MB25.1 TP1MC19.1 U65.R3(A9) U66.R3(A9) U67.M3(A9) ; also on sheet 19
DDR1_A10: RN13.3(R3A) TP1MA8.1 TP1MB8.1 TP1MC6.1 U65.L7(A10) U66.L7(A10) U67.H7(A10/AP) ; also on sheet 19
DDR1_A11: RN17.4(R4A) TP1MA18.1 TP1MB18.1 TP1MC20.1 U65.R7(A11) U66.R7(A11) U67.M7(A11) ; also on sheet 19
DDR1_A12: RN15.1(R1A) TP1MA13.1 TP1MB13.1 TP1MC15.1 U65.N7(A12) U66.N7(A12) U67.K7(A12/~{BC}) ; also on sheet 19
DDR1_A13: RN6.3(R3A) TP1MA23.1 TP1MB23.1 TP1MC23.1 U65.T3(A13) U66.T3(A13) U67.N3(A13) ; also on sheet 19
DDR1_A14: RN17.2(R2A) TP1MA24.1 TP1MB24.1 TP1MC24.1 U65.T7(A14) U66.T7(A14) U67.N7(A14/NC) ; also on sheet 19
DDR1_A15: RN13.1(R1A) TP1MA11.1 TP1MB11.1 TP1MC9.1 U65.M7(NC.M7/A15) U66.M7(NC.M7/A15) U67.J7(A15/NC) ; also on sheet 19
DDR1_BA0: RN2.4(R4A) TP1MA9.1 TP1MB9.1 TP1MC10.1 U65.M2(BA0) U66.M2(BA0) U67.J2(BA0) ; also on sheet 19
DDR1_BA1: RN15.3(R3A) TP1MA12.1 TP1MB12.1 TP1MC12.1 U65.N8(BA1) U66.N8(BA1) U67.K8(BA1) ; also on sheet 19
DDR1_BA2: RN15.2(R2A) TP1MA15.1 TP1MB15.1 TP1MC11.1 U65.M3(BA2) U66.M3(BA2) U67.J3(BA2) ; also on sheet 19
DDR1_CASN: RN2.2(R2A) TP1MA3.1 TP1MB3.1 TP1MC5.1 U65.K3(CAS#) U66.K3(CAS#) U67.G3(~{CAS}) ; also on sheet 19
DDR1_CKE: R689.1 R804.1 TP1MA2.1 TP1MB2.1 TP1MC3.1 U65.K9(CKE) U66.K9(CKE) U67.G9(CKE) ; also on sheet 19
DDR1_CLK0: R684.1 TP1MA1.1 TP1MB1.1 TP1MC2.1 U65.J7(CK) U66.J7(CK) U67.F7(CK) ; also on sheet 19
DDR1_CLK0N: R687.1 TP1MA4.1 TP1MB4.1 TP1MC4.1 U65.K7(CK#) U66.K7(CK#) U67.G7(~{CK}) ; also on sheet 19
DDR1_CSN0: RN2.3(R3A) TP1MA10.1 TP1MB10.1 TP1MC8.1 U65.L2(CS#) U66.L2(CS#) U67.H2(~{CS}) ; also on sheet 19
DDR1_D0: U65.H7(DQ7) ; also on sheet 19
DDR1_D1: U65.F8(DQ3) ; also on sheet 19
DDR1_D2: U65.F7(DQ1) ; also on sheet 19
DDR1_D3: U65.H8(DQ5) ; also on sheet 19
DDR1_D4: U65.E3(DQ0) ; also on sheet 19
DDR1_D5: U65.H3(DQ4) ; also on sheet 19
DDR1_D6: U65.F2(DQ2) ; also on sheet 19
DDR1_D7: U65.G2(DQ6) ; also on sheet 19
DDR1_D8: U65.A2(DQ13) ; also on sheet 19
DDR1_D9: U65.B8(DQ14) ; also on sheet 19
DDR1_D10: U65.A7(DQ12) ; also on sheet 19
DDR1_D11: U65.C8(DQ10) ; also on sheet 19
DDR1_D12: U65.C3(DQ9) ; also on sheet 19
DDR1_D13: U65.D7(DQ8) ; also on sheet 19
DDR1_D14: U65.A3(DQ15) ; also on sheet 19
DDR1_D15: U65.C2(DQ11) ; also on sheet 19
DDR1_D16: U66.F8(DQ3) ; also on sheet 19
DDR1_D17: U66.H8(DQ5) ; also on sheet 19
DDR1_D18: U66.F7(DQ1) ; also on sheet 19
DDR1_D19: U66.F2(DQ2) ; also on sheet 19
DDR1_D20: U66.E3(DQ0) ; also on sheet 19
DDR1_D21: U66.G2(DQ6) ; also on sheet 19
DDR1_D22: U66.H7(DQ7) ; also on sheet 19
DDR1_D23: U66.H3(DQ4) ; also on sheet 19
DDR1_D24: U66.C3(DQ9) ; also on sheet 19
DDR1_D25: U66.A7(DQ12) ; also on sheet 19
DDR1_D26: U66.B8(DQ14) ; also on sheet 19
DDR1_D27: U66.A3(DQ15) ; also on sheet 19
DDR1_D28: U66.C8(DQ10) ; also on sheet 19
DDR1_D29: U66.C2(DQ11) ; also on sheet 19
DDR1_D30: U66.A2(DQ13) ; also on sheet 19
DDR1_D31: U66.D7(DQ8) ; also on sheet 19
DDR1_DQM0: U65.E7(LDM) ; also on sheet 19
DDR1_DQM1: U65.D3(UDM) ; also on sheet 19
DDR1_DQM2: U66.E7(LDM) ; also on sheet 19
DDR1_DQM3: U66.D3(UDM) ; also on sheet 19
DDR1_DQM_ECC: U67.B7(DM/TDQS) ; also on sheet 19
DDR1_DQS0: U65.F3(LDQS) ; also on sheet 19
DDR1_DQS1: U65.C7(UDQS) ; also on sheet 19
DDR1_DQS2: U66.F3(LDQS) ; also on sheet 19
DDR1_DQS3: U66.C7(UDQS) ; also on sheet 19
DDR1_DQS_ECC: U67.C3(DQS) ; also on sheet 19
DDR1_DQSN0: U65.G3(LDQS#) ; also on sheet 19
DDR1_DQSN1: U65.B7(UDQS#) ; also on sheet 19
DDR1_DQSN2: U66.G3(LDQS#) ; also on sheet 19
DDR1_DQSN3: U66.B7(UDQS#) ; also on sheet 19
DDR1_DQSN_ECC: U67.D3(~{DQS}) ; also on sheet 19
DDR1_ECC_D0: U67.E8(DQ5) ; also on sheet 19
DDR1_ECC_D1: U67.C8(DQ3) ; also on sheet 19
DDR1_ECC_D2: U67.E3(DQ4) ; also on sheet 19
DDR1_ECC_D3: U67.D2(DQ6) ; also on sheet 19
DDR1_ECC_D4: U67.C7(DQ1) ; also on sheet 19
DDR1_ECC_D5: U67.E7(DQ7) ; also on sheet 19
DDR1_ECC_D6: U67.C2(DQ2) ; also on sheet 19
DDR1_ECC_D7: U67.B3(DQ0) ; also on sheet 19
DDR1_ODT0: RN2.1(R1A) TP1MA5.1 TP1MB5.1 TP2MC1.1 U65.K1(ODT) U66.K1(ODT) U67.G1(ODT) ; also on sheet 19
DDR1_RASN: RN13.4(R4A) TP1MA6.1 TP1MB6.1 TP1MC1.1 U65.J3(RAS#) U66.J3(RAS#) U67.F3(~{RAS}) ; also on sheet 19
DDR1_RST: U65.T2(RSTn) U66.T2(RSTn) U67.N2(~{RESET}) ; also on sheet 19 71
DDR1_WEN: RN13.2(R2A) TP1MA7.1 TP1MB7.1 TP1MC7.1 U65.L3(WE#) U66.L3(WE#) U67.H3(~{WE}) ; also on sheet 19
DDR2_A0: TP2MA15.1 TP2MB15.1 U68.K3(A0) U69.K3(A0) U115.K3(A0) U116.K3(A0) ; also on sheet 20 48
DDR2_A1: TP2MA19.1 TP2MB19.1 U68.L7(A1) U69.L7(A1) U115.L7(A1) U116.L7(A1) ; also on sheet 20 48
DDR2_A2: TP2MA20.1 TP2MB20.1 U68.L3(A2) U69.L3(A2) U115.L3(A2) U116.L3(A2) ; also on sheet 20 48
DDR2_A3: TP2MA14.1 TP2MB14.1 U68.K2(A3) U69.K2(A3) U115.K2(A3) U116.K2(A3) ; also on sheet 20 48
DDR2_A4: TP2MA17.1 TP2MB17.1 U68.L8(A4) U69.L8(A4) U115.L8(A4) U116.L8(A4) ; also on sheet 20 48
DDR2_A5: TP2MA18.1 TP2MB18.1 U68.L2(A5) U69.L2(A5) U115.L2(A5) U116.L2(A5) ; also on sheet 20 48
DDR2_A6: TP2MA24.1 TP2MB24.1 U68.M8(A6) U69.M8(A6) U115.M8(A6) U116.M8(A6) ; also on sheet 20 48
DDR2_A7: TP2MA23.1 TP2MB23.1 U68.M2(A7) U69.M2(A7) U115.M2(A7) U116.M2(A7) ; also on sheet 20 48
DDR2_A8: TP2MA27.1 TP2MB27.1 U68.N8(A8) U69.N8(A8) U115.N8(A8) U116.N8(A8) ; also on sheet 20 48
DDR2_A9: TP2MA21.1 TP2MB21.1 U68.M3(A9) U69.M3(A9) U115.M3(A9) U116.M3(A9) ; also on sheet 20 48
DDR2_A10: TP2MA7.1 TP2MB7.1 U68.H7(A10/AP) U69.H7(A10/AP) U115.H7(A10/AP) U116.H7(A10/AP) ; also on sheet 20 48
DDR2_A11: TP2MA22.1 TP2MB22.1 U68.M7(A11) U69.M7(A11) U115.M7(A11) U116.M7(A11) ; also on sheet 20 48
DDR2_A12: TP2MA16.1 TP2MB16.1 U68.K7(A12/~{BC}) U69.K7(A12/~{BC}) U115.K7(A12/~{BC}) U116.K7(A12/~{BC}) ; also on sheet 20 48
DDR2_A13: TP2MA26.1 TP2MB26.1 U68.N3(A13) U69.N3(A13) U115.N3(A13) U116.N3(A13) ; also on sheet 20 48
DDR2_A14: TP2MA25.1 TP2MB25.1 U68.N7(A14/NC) U69.N7(A14/NC) U115.N7(A14/NC) U116.N7(A14/NC) ; also on sheet 20 48
DDR2_A15: TP2MA12.1 TP2MB12.1 U68.J7(A15/NC) U69.J7(A15/NC) U115.J7(A15/NC) U116.J7(A15/NC) ; also on sheet 20 48
DDR2_BA0: TP2MA10.1 TP2MB10.1 U68.J2(BA0) U69.J2(BA0) U115.J2(BA0) U116.J2(BA0) ; also on sheet 20 48
DDR2_BA1: TP2MA13.1 TP2MB13.1 U68.K8(BA1) U69.K8(BA1) U115.K8(BA1) U116.K8(BA1) ; also on sheet 20 48
DDR2_BA2: TP2MA11.1 TP2MB11.1 U68.J3(BA2) U69.J3(BA2) U115.J3(BA2) U116.J3(BA2) ; also on sheet 20 48
DDR2_CASN: TP2MA6.1 TP2MB6.1 U68.G3(~{CAS}) U69.G3(~{CAS}) U115.G3(~{CAS}) U116.G3(~{CAS}) ; also on sheet 20 48
DDR2_CKE: R805.1 TP2MA1.1 TP2MB1.1 U68.G9(CKE) U69.G9(CKE) U115.G9(CKE) U116.G9(CKE) ; also on sheet 20 48
DDR2_CLK0: TP2MA4.1 TP2MB4.1 U68.F7(CK) U69.F7(CK) U115.F7(CK) U116.F7(CK) ; also on sheet 20 48
DDR2_CLK0N: TP2MA5.1 TP2MB5.1 U68.G7(~{CK}) U69.G7(~{CK}) U115.G7(~{CK}) U116.G7(~{CK}) ; also on sheet 20 48
DDR2_CSN0: TP2MA8.1 TP2MB8.1 U68.H2(~{CS}) U69.H2(~{CS}) U115.H2(~{CS}) U116.H2(~{CS}) ; also on sheet 20 48
DDR2_D0: U115.E7(DQ7) ; also on sheet 20
DDR2_D1: U115.D2(DQ6) ; also on sheet 20
DDR2_D2: U115.C8(DQ3) ; also on sheet 20
DDR2_D3: U115.E8(DQ5) ; also on sheet 20
DDR2_D4: U115.C7(DQ1) ; also on sheet 20
DDR2_D5: U115.E3(DQ4) ; also on sheet 20
DDR2_D6: U115.C2(DQ2) ; also on sheet 20
DDR2_D7: U115.B3(DQ0) ; also on sheet 20
DDR2_D8: U69.E3(DQ4) ; also on sheet 20
DDR2_D9: U69.E7(DQ7) ; also on sheet 20
DDR2_D10: U69.E8(DQ5) ; also on sheet 20
DDR2_D11: U69.C7(DQ1) ; also on sheet 20
DDR2_D12: U69.C8(DQ3) ; also on sheet 20
DDR2_D13: U69.B3(DQ0) ; also on sheet 20
DDR2_D14: U69.C2(DQ2) ; also on sheet 20
DDR2_D15: U69.D2(DQ6) ; also on sheet 20
DDR2_D16: U116.C7(DQ1) ; also on sheet 20
DDR2_D17: U116.C2(DQ2) ; also on sheet 20
DDR2_D18: U116.B3(DQ0) ; also on sheet 20
DDR2_D19: U116.C8(DQ3) ; also on sheet 20
DDR2_D20: U116.E8(DQ5) ; also on sheet 20
DDR2_D21: U116.E7(DQ7) ; also on sheet 20
DDR2_D22: U116.E3(DQ4) ; also on sheet 20
DDR2_D23: U116.D2(DQ6) ; also on sheet 20
DDR2_D24: U68.C7(DQ1) ; also on sheet 20
DDR2_D25: U68.E8(DQ5) ; also on sheet 20
DDR2_D26: U68.C8(DQ3) ; also on sheet 20
DDR2_D27: U68.E3(DQ4) ; also on sheet 20
DDR2_D28: U68.E7(DQ7) ; also on sheet 20
DDR2_D29: U68.D2(DQ6) ; also on sheet 20
DDR2_D30: U68.B3(DQ0) ; also on sheet 20
DDR2_D31: U68.C2(DQ2) ; also on sheet 20
DDR2_DQM0: U115.B7(DM/TDQS) ; also on sheet 20
DDR2_DQM1: U69.B7(DM/TDQS) ; also on sheet 20
DDR2_DQM2: U116.B7(DM/TDQS) ; also on sheet 20
DDR2_DQM3: U68.B7(DM/TDQS) ; also on sheet 20
DDR2_DQS0: U115.C3(DQS) ; also on sheet 20
DDR2_DQS1: U69.C3(DQS) ; also on sheet 20
DDR2_DQS2: U116.C3(DQS) ; also on sheet 20
DDR2_DQS3: U68.C3(DQS) ; also on sheet 20
DDR2_DQSN0: U115.D3(~{DQS}) ; also on sheet 20
DDR2_DQSN1: U69.D3(~{DQS}) ; also on sheet 20
DDR2_DQSN2: U116.D3(~{DQS}) ; also on sheet 20
DDR2_DQSN3: U68.D3(~{DQS}) ; also on sheet 20
DDR2_ODT0: TP2MA3.1 TP2MB3.1 U68.G1(ODT) U69.G1(ODT) U115.G1(ODT) U116.G1(ODT) ; also on sheet 20 48
DDR2_RASN: TP2MA2.1 TP2MB2.1 U68.F3(~{RAS}) U69.F3(~{RAS}) U115.F3(~{RAS}) U116.F3(~{RAS}) ; also on sheet 20 48
DDR2_RST: U68.N2(~{RESET}) U69.N2(~{RESET}) U115.N2(~{RESET}) U116.N2(~{RESET}) ; also on sheet 20 71
DDR2_WEN: TP2MA9.1 TP2MB9.1 U68.H3(~{WE}) U69.H3(~{WE}) U115.H3(~{WE}) U116.H3(~{WE}) ; also on sheet 20 48
DDR_VREFSTL1: C203.1 C204.1 C205.1 C617.1 C618.1 C619.1 U65.H1(VREFDQ) U65.M8(VREFCA) U66.H1(VREFDQ) U66.M8(VREFCA) U67.E1(VREFDQ) U67.J8(VREFCA) ; also on sheet 19 70
DDR_VREFSTL2: C177.1 C178.1 C197.1 C198.1 C628.1 C629.1 C651.1 C652.1 U68.E1(VREFDQ) U68.J8(VREFCA) U69.E1(VREFDQ) U69.J8(VREFCA) U115.E1(VREFDQ) U115.J8(VREFCA) U116.E1(VREFDQ) U116.J8(VREFCA) ; also on sheet 20 70
IN2_VDDS18V: C699.1 R800.1 U136.6(IN2)
MMC2_BOOTn: U136.3(D1) ; also on sheet 9 17 18
VAYU_VDDA_DEBUG1.8: C414.2 C420.1 C427.1 C490.1 E4.1 U52.N11(VDDA_DEBUG) U52.N12(VDDA_DSP_EVE)
VAYU_VDDA_IVA1.8: C415.2 C422.1 C429.1 C497.1 E3.1 U52.R14(VDDA_GPU) U52.R17(VDDA_IVA)
VAYU_VDDA_MPU1.8: C413.1 C419.1 C426.1 C507.2 E5.1 U52.M14(VDDA_ABE_PER) U52.N16(VDDA_MPU)
VAYU_VDDA_VIDEO1.8: C412.2 C418.1 C425.1 C491.1 E6.1 U52.P14(VDDA_VIDEO) U52.P15(VDDA_GMAC_CORE) U52.P16(VDDA_DDR)
VTT: C164.1 C165.1 C175.1 C180.1 C206.1 C207.1 C627.1 C635.1 C643.1 C654.1 C662.1 C663.1 R689.2 RN2.5(R4B) RN2.6(R3B) RN2.7(R2B) RN2.8(R1B) RN4.5(R4B) RN4.6(R3B) RN4.7(R2B) RN4.8(R1B) RN6.5(R4B) RN6.6(R3B) RN6.7(R2B) RN6.8(R1B) RN13.5(R4B) RN13.6(R3B) RN13.7(R2B) RN13.8(R1B) RN15.5(R4B) RN15.6(R3B) RN15.7(R2B) RN15.8(R1B) RN17.5(R4B) RN17.6(R3B) RN17.7(R2B) RN17.8(R1B) ; also on sheet 48 70
ZQ_DBYTE1: R694.1 U115.H8(ZQ)
ZQ_DBYTE2: R289.1 U69.H8(ZQ)
ZQ_DBYTE3: R695.1 U116.H8(ZQ)
ZQ_DBYTE4: R288.1 U68.H8(ZQ)
ZQ_DBYTE4_1: R693.1 U67.H8(ZQ)
N35610: R692.1 U65.L8(ZQ)
N35614: R691.1 U66.L8(ZQ)
N21683151: R801.2 U136.4(ILIM)
N24036072: C599.1 R684.2 R687.2
N39334441: TP51.1 U52.K14(VPP)

Not connected (* = marked no-connect by the designer): U52 A27(IFORCE) B28(VSENSE) Y10(ATESTV); U65 J1(NC.J1) J9(NC.J9) L1(NC.L1) L9(NC.L9); U66 J1(NC.J1) J9(NC.J9) L1(NC.L1) L9(NC.L9); U67 A3(NC.1) A7(~{TDQS}) F1(NC.2) F9(NC.3) H1(NC.4) H9(NC.5); U68 A3(NC.1) A7(~{TDQS}) F1(NC.2) F9(NC.3) H1(NC.4) H9(NC.5); U69 A3(NC.1) A7(~{TDQS}) F1(NC.2) F9(NC.3) H1(NC.4) H9(NC.5); U115 A3(NC.1) A7(~{TDQS}) F1(NC.2) F9(NC.3) H1(NC.4) H9(NC.5); U116 A3(NC.1) A7(~{TDQS}) F1(NC.2) F9(NC.3) H1(NC.4) H9(NC.5); U136 1(STAT)*

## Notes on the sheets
sheet 35
- ER23
- D1=1, IN1 NOR BOOT
  D1=0,IN2 eMMC BOOT
- BOOT SWITCHES DEFAULT AS PULLUPS. SWITCH
  CLOSED IS PULL DOWN TO SELECT FUNCTION.
sheet 38
- 1.8 VOLT
sheet 39
- 1.X VOLT
- 1.X VOLT
- 1.X VOLT
- 1.X VOLT
- CAPACITANCE      SIZE
  .1uF             0201
  .22uF            0201
  .47uF            0201
  1uF              0201
  2.2uF            0402
  4.7uF            0402
  10uF             0402
  22uF             0603
- 1.X VOLT
sheet 42
- ER37
- ER37
- ER37
- ER18
sheet 45
- MEMORY 3
- MEMORY 1
- MEMORY 4
- MEMORY 2
- This section is an outline of vias labeled as Testpoints
  in the schematic. This allows us to determine pwb line
  lengths for memory to memory and CPU to memory it is
  purely a visibility tool no actual "component" is used
  the vias are just replaced with a via that is  labeled a
  test point
sheet 46
- ER37
- ER37
- ER37
- ER37
- ER18
